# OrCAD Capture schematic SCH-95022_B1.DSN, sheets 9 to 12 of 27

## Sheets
9 Page10 BOOT CFG: size A2
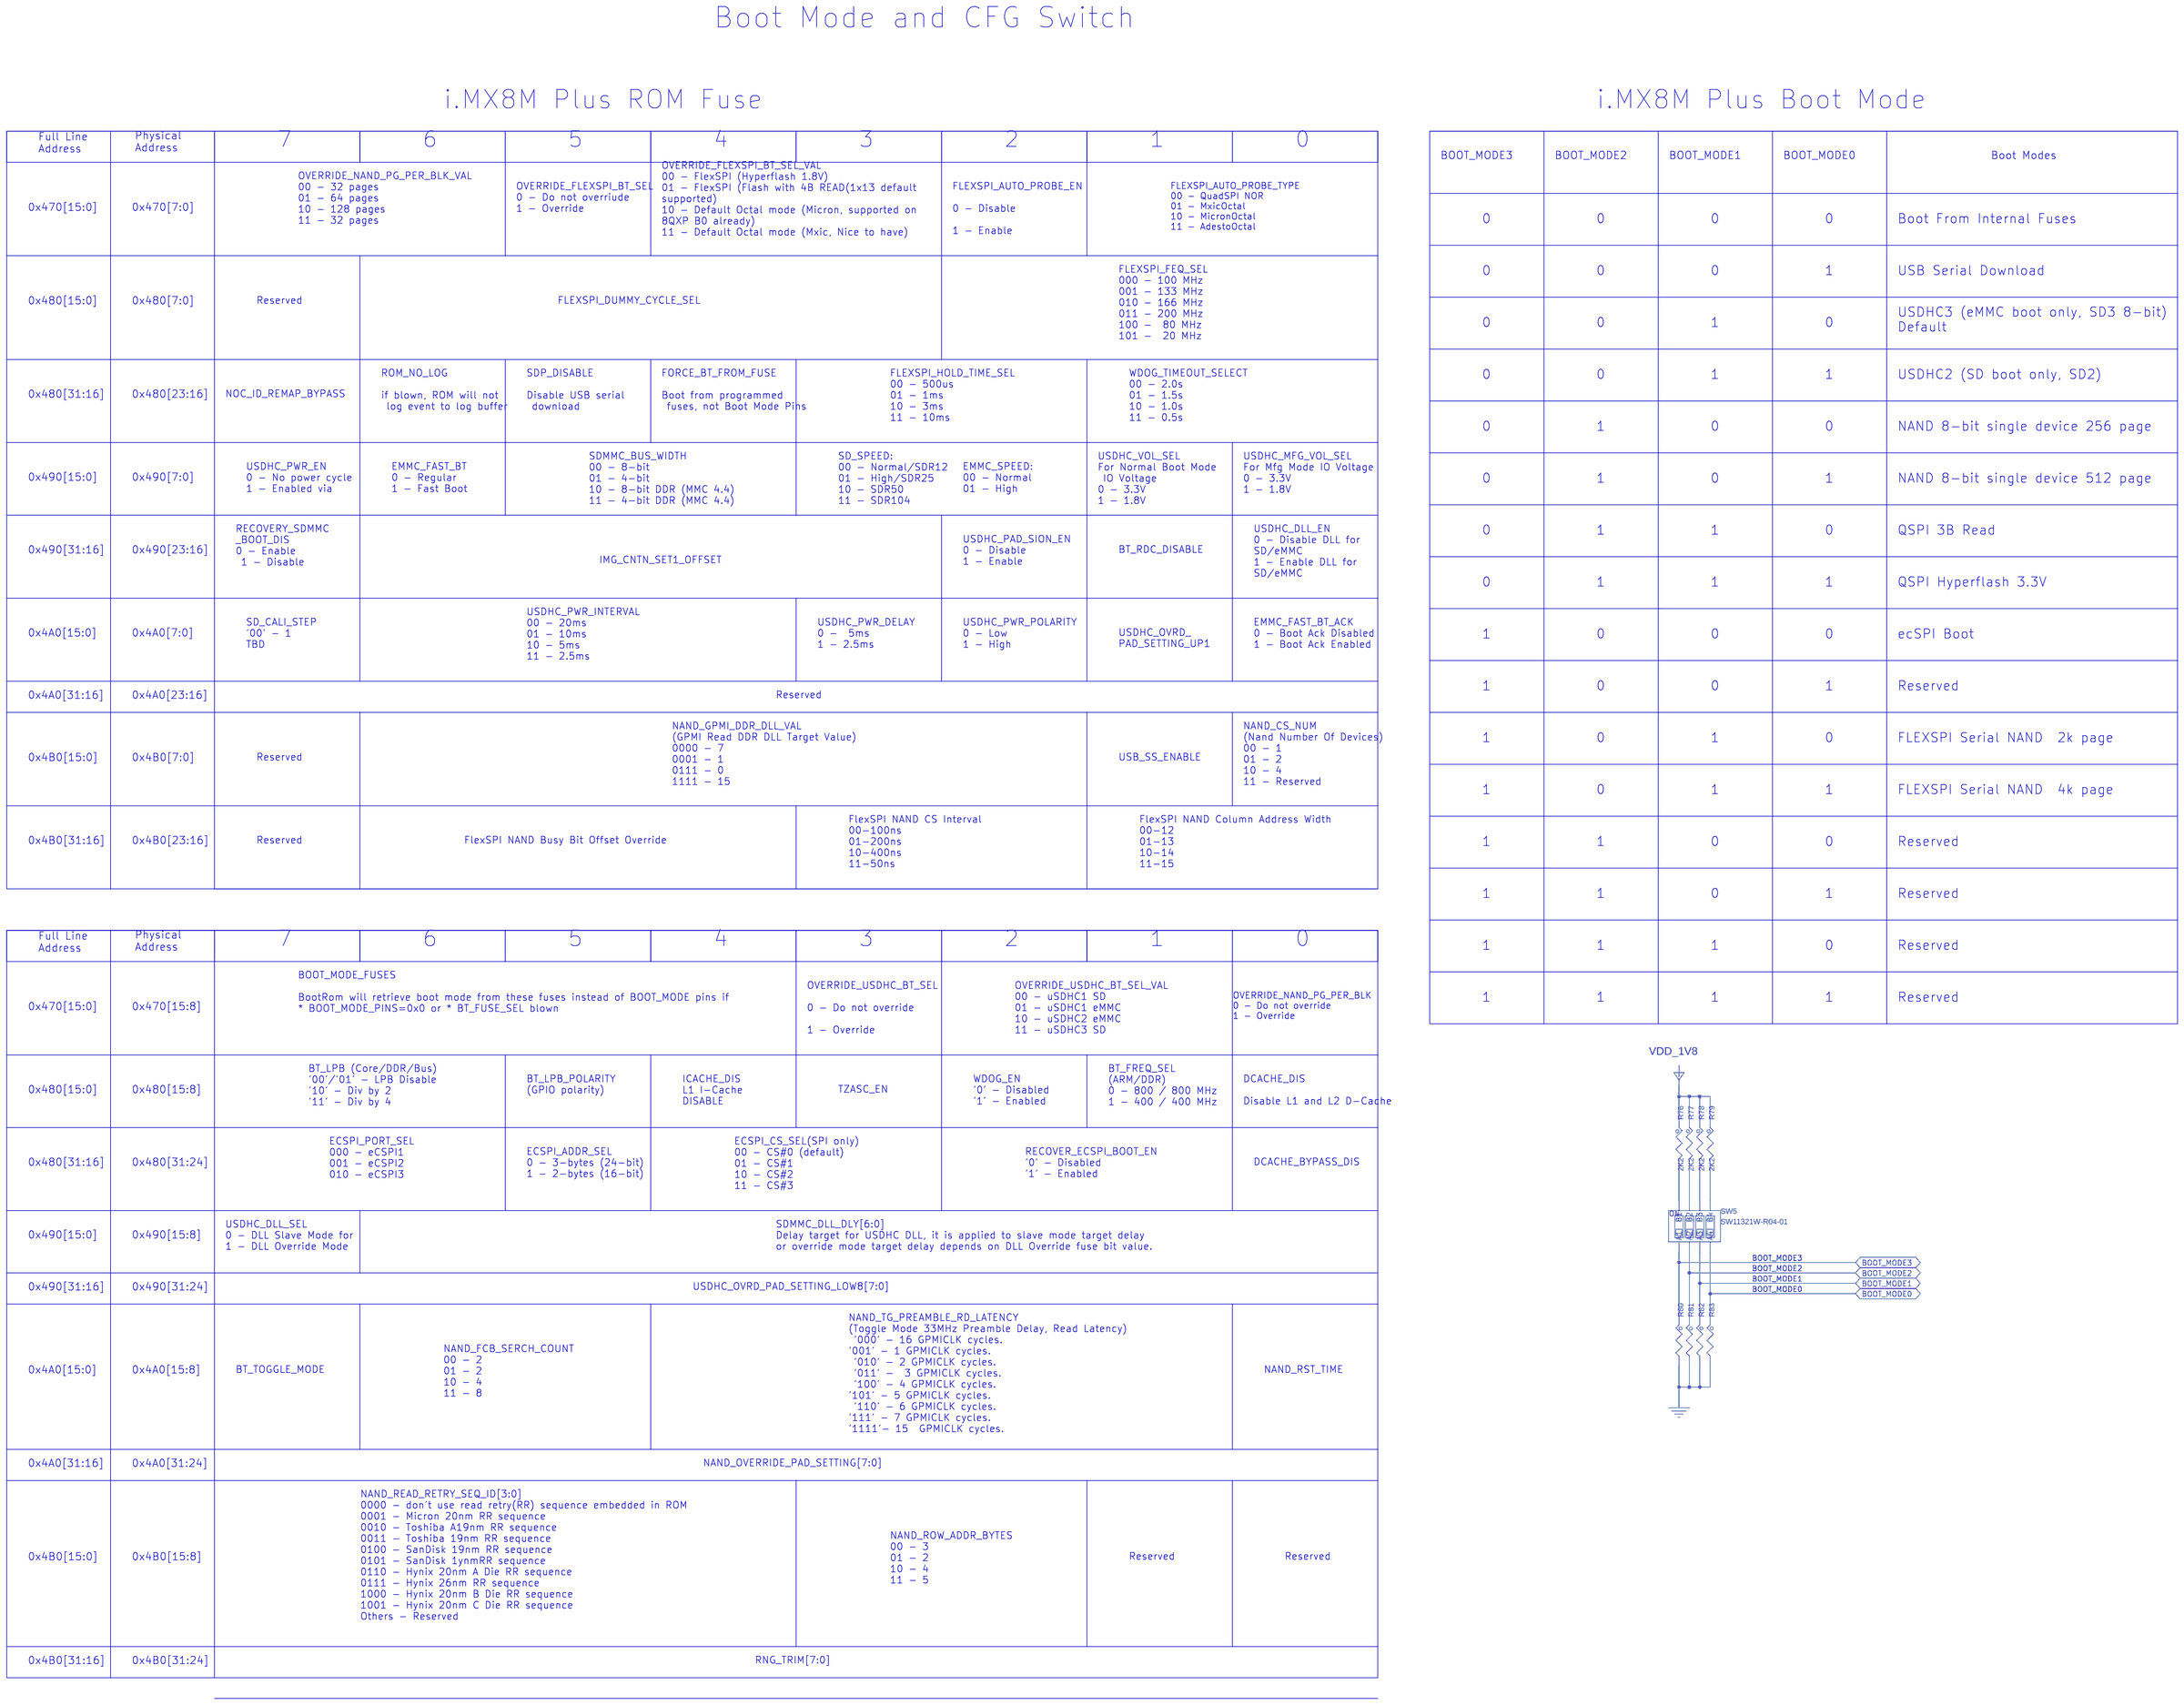
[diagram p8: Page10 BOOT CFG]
10 Page11 PMIC: size C
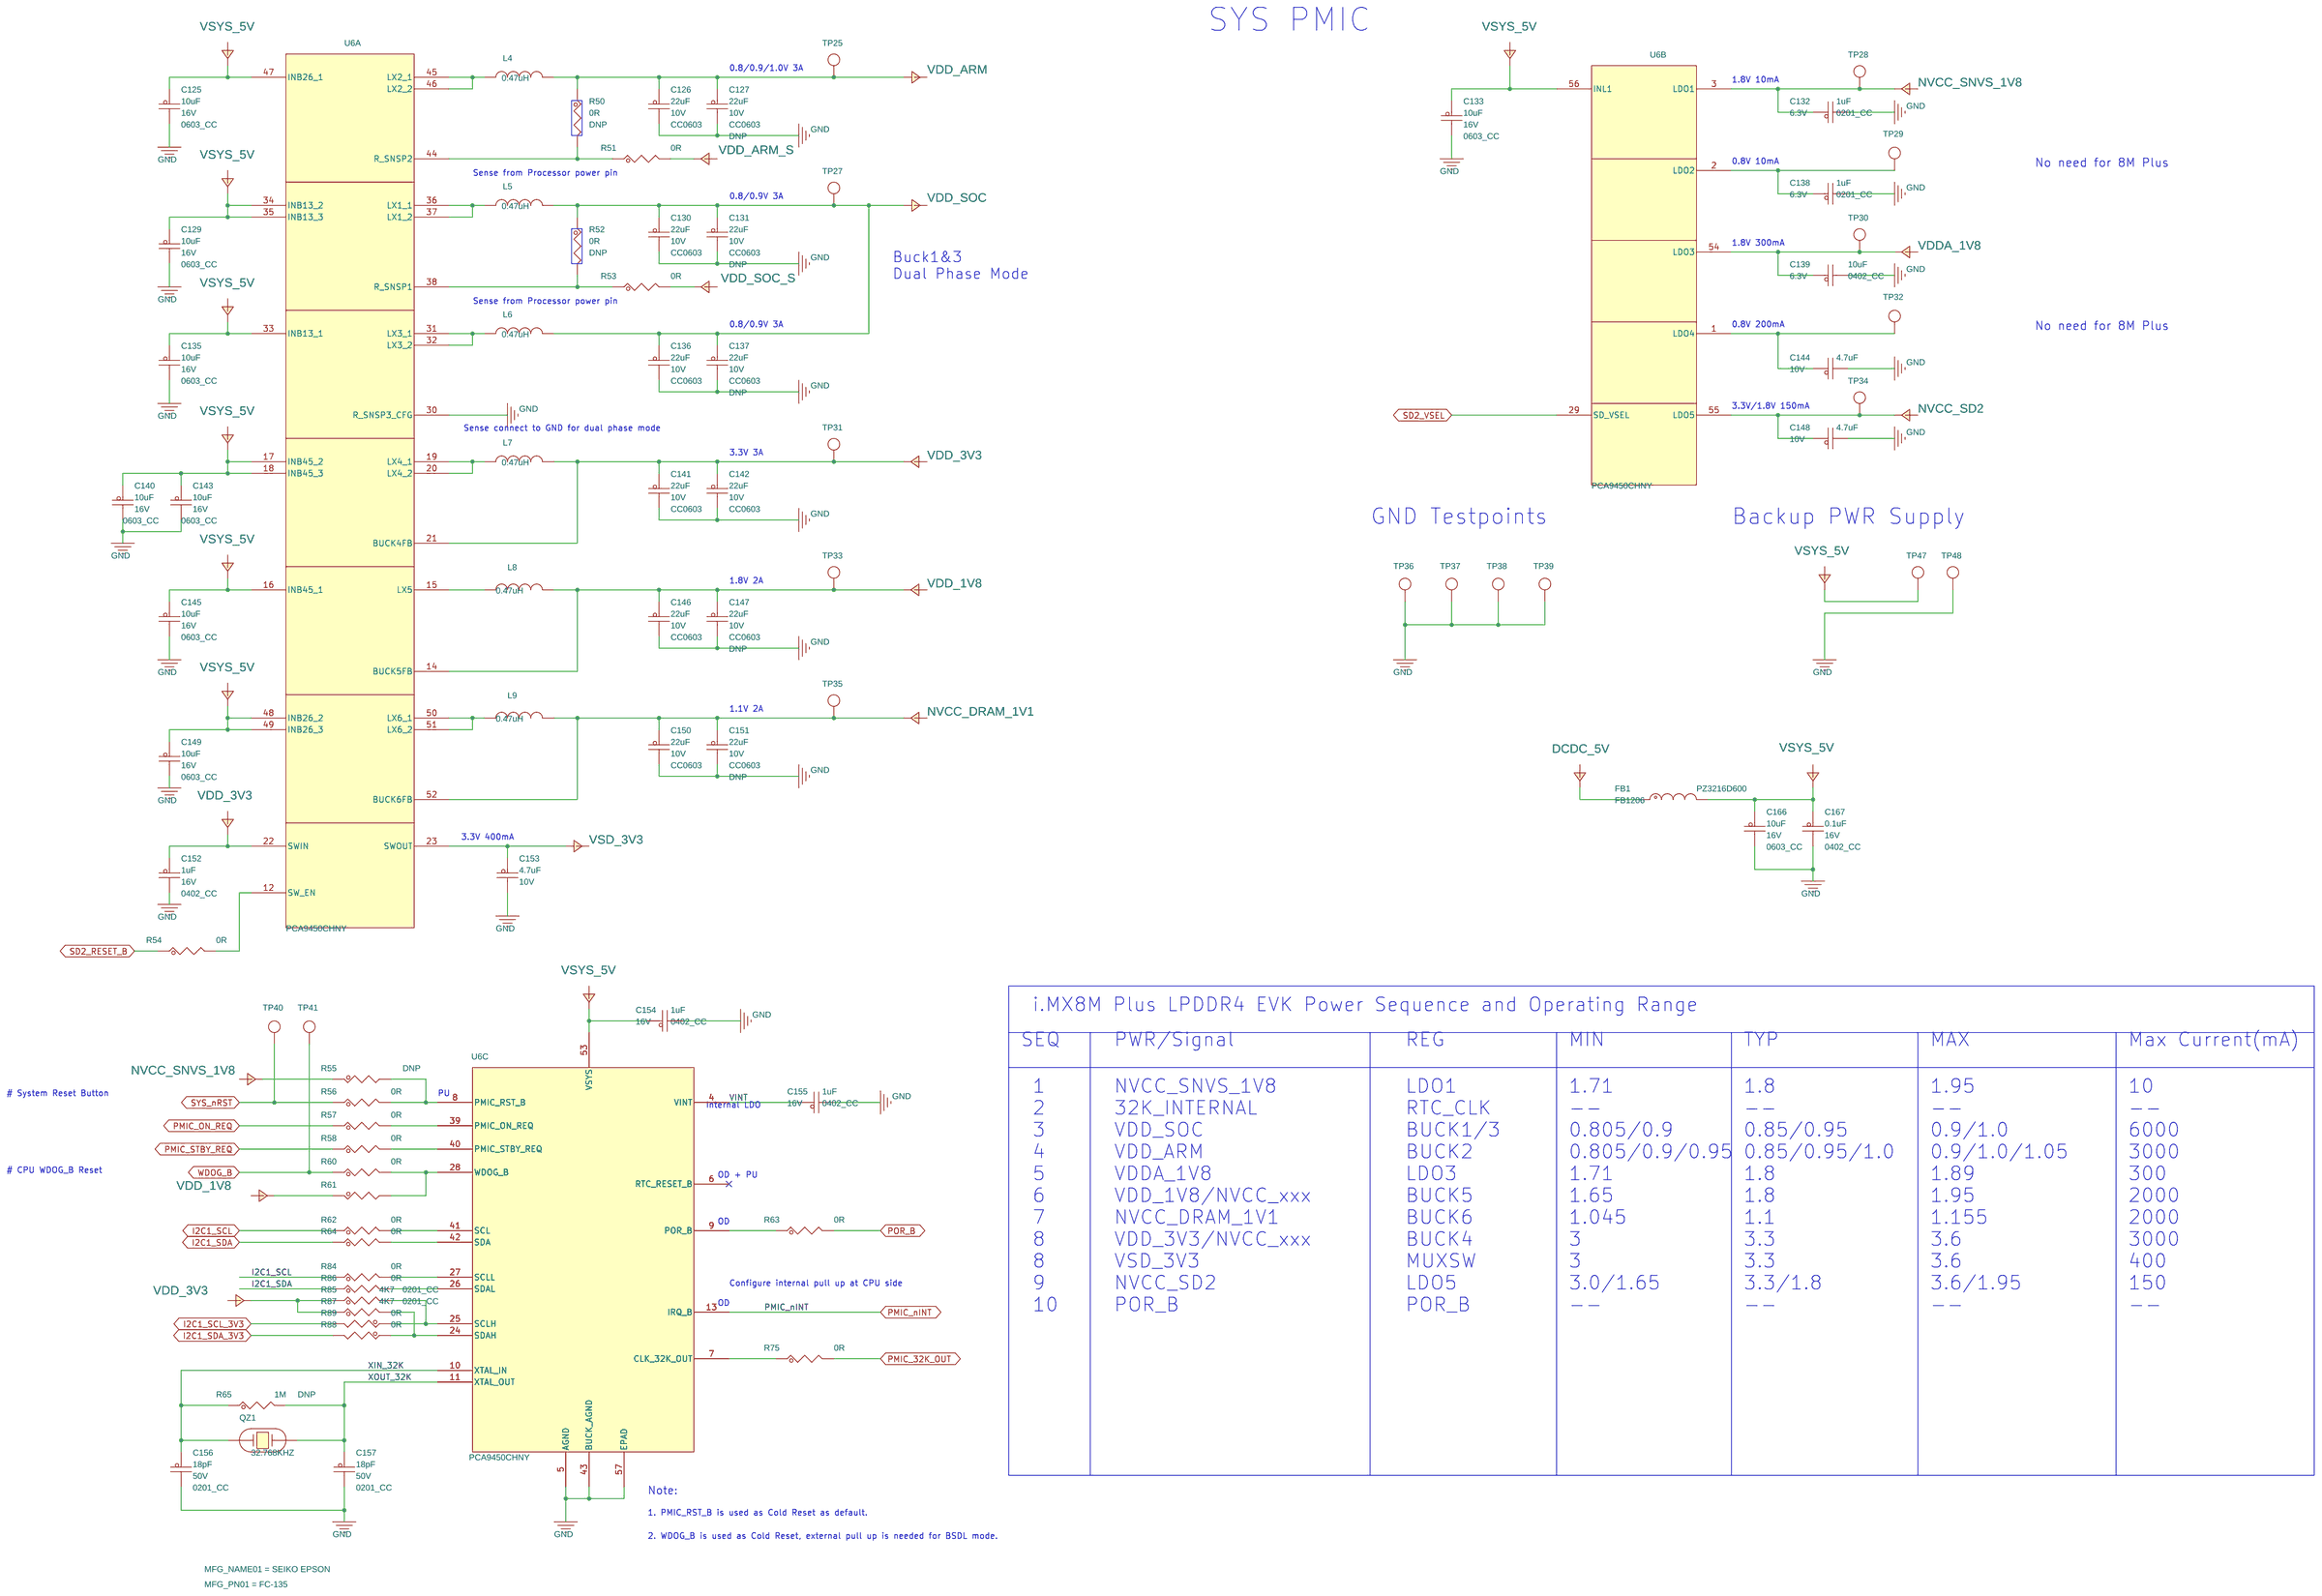
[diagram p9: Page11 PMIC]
11 Page12 SYS PWR: size C
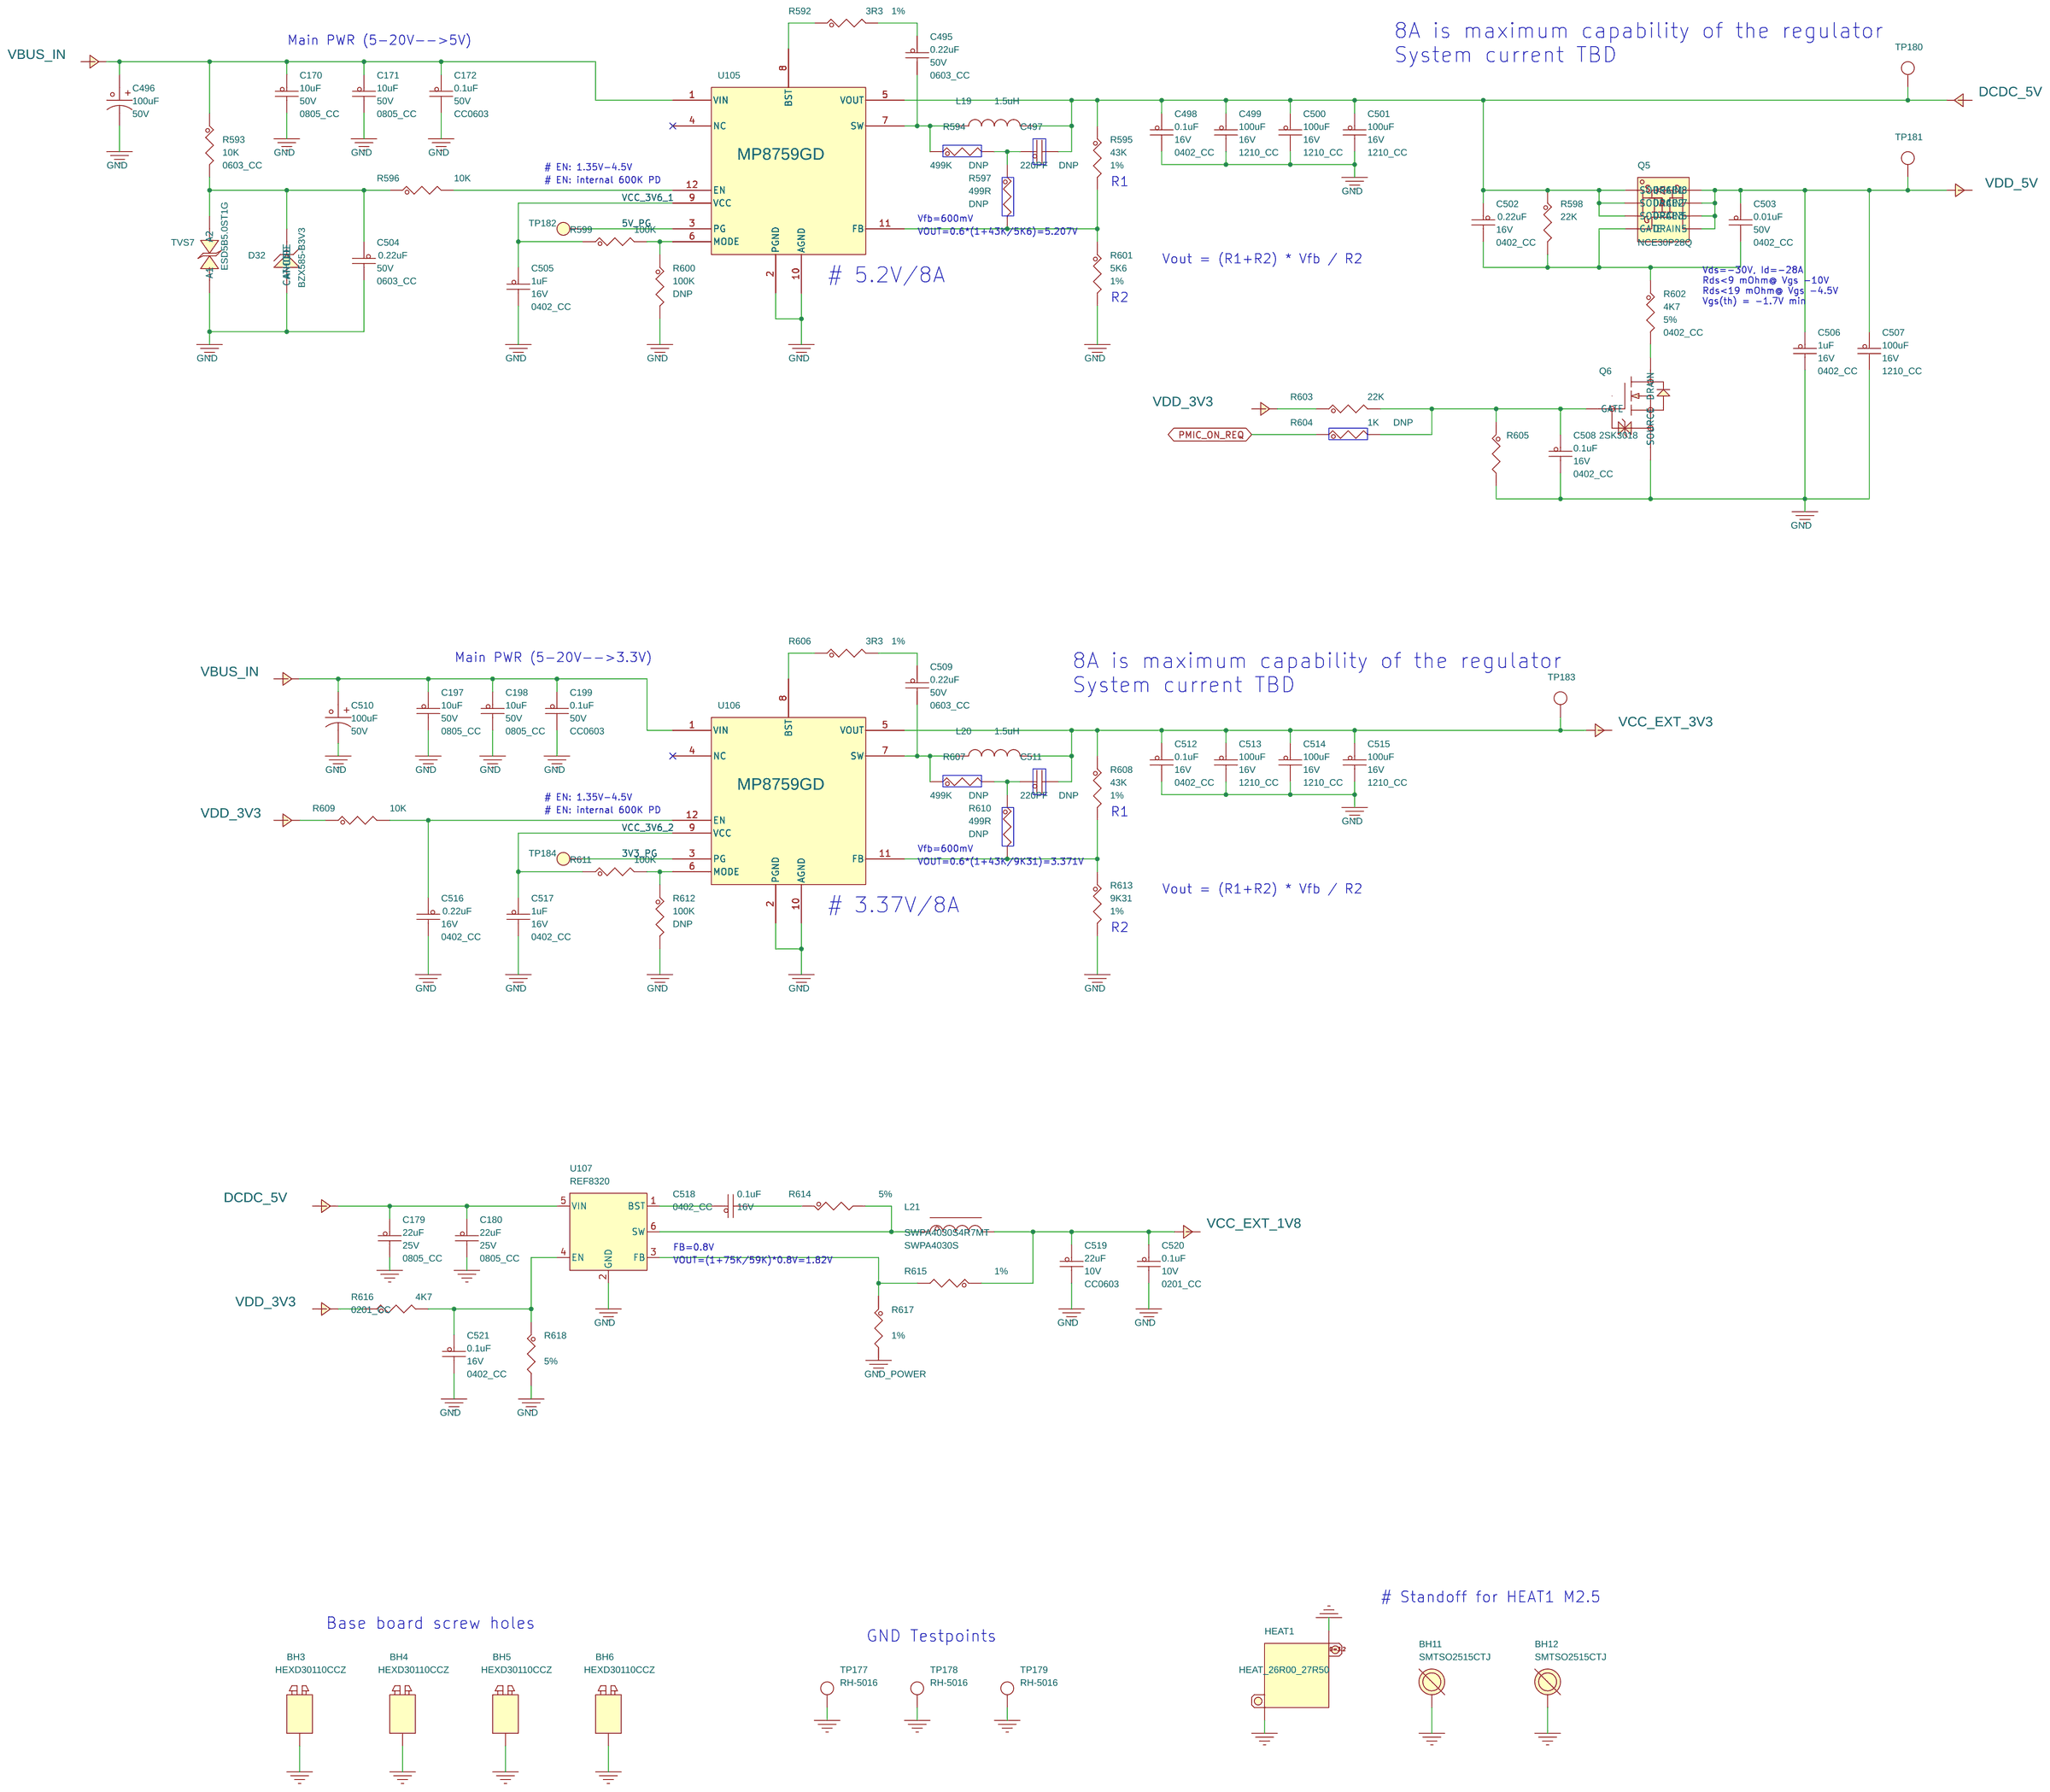
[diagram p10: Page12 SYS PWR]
12 Page13 USB PWR TYPE-C PD: size C
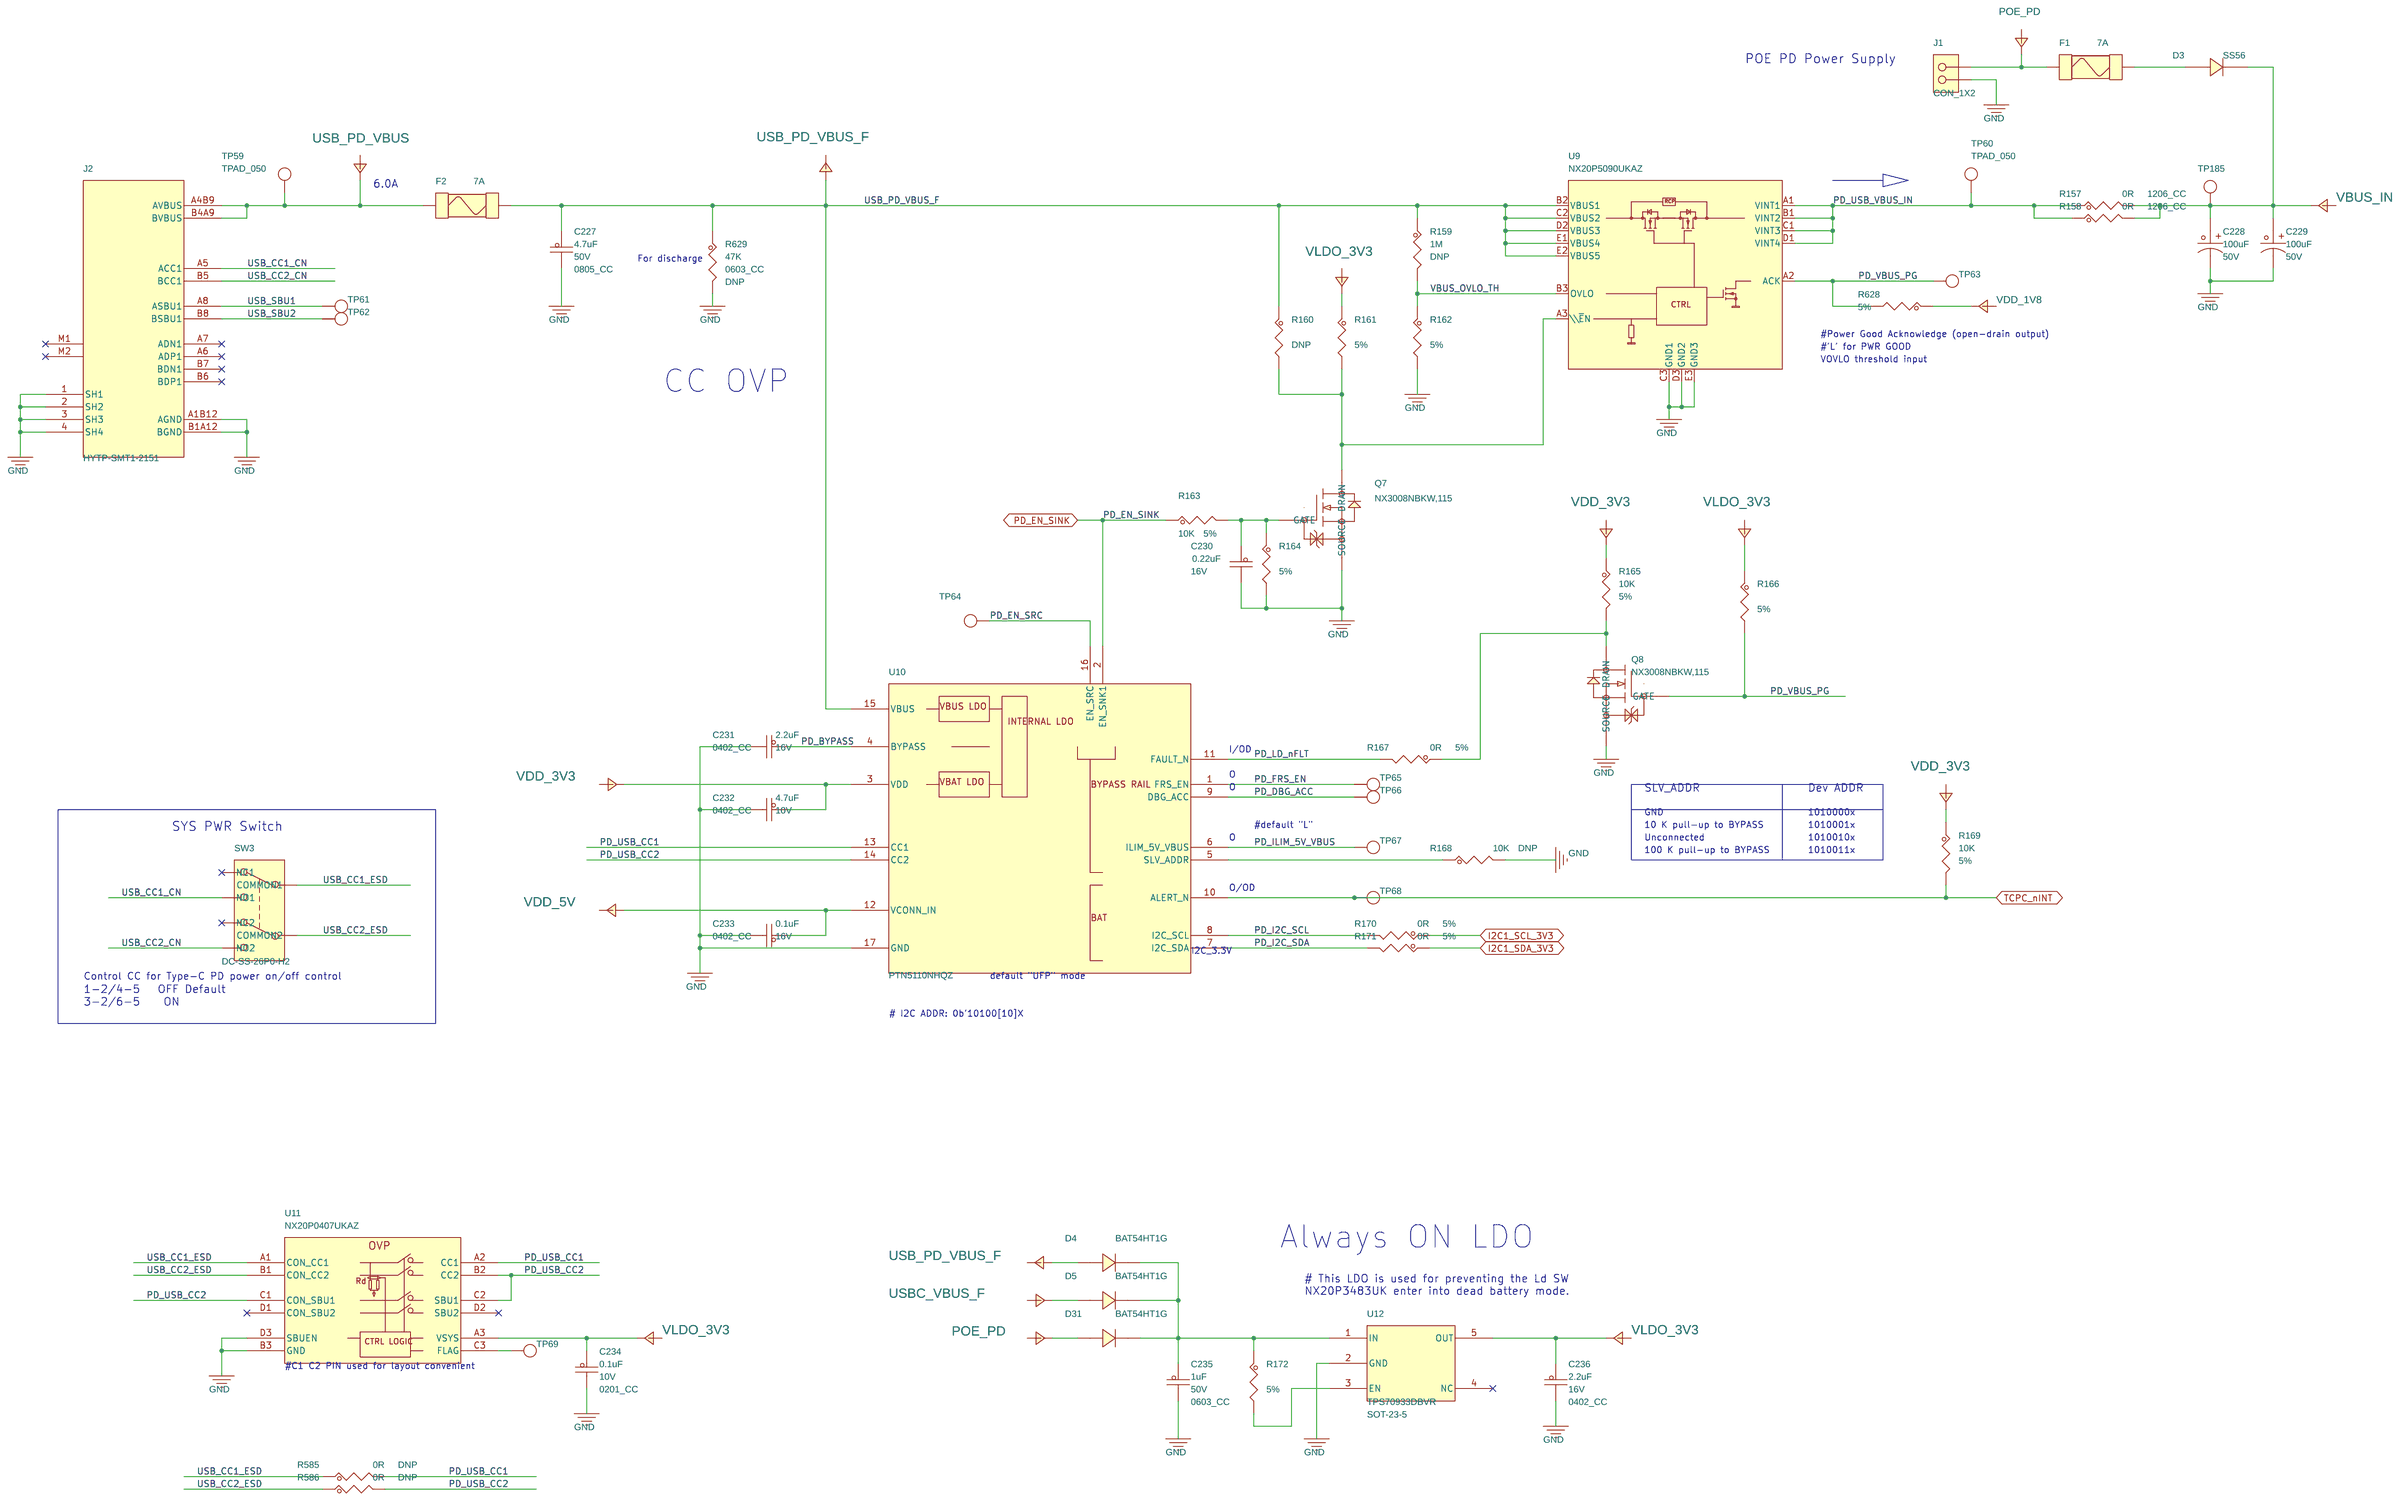
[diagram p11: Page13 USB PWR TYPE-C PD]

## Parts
sheet Page10 BOOT CFG
R76  2K2  [0402_CC]
R77  2K2  [0402_CC]
R78  2K2  [0402_CC]
R79  2K2  [0402_CC]
R80  100K  [0402_CC]
R81  100K  [0402_CC]
R82  100K  [0402_CC]
R83  100K  [0402_CC]
SW5  SW11321W-R04-01  [SW_1P27_4P]
sheet Page11 PMIC
C125  10uF  [0603_CC]
C126  22uF  [CC0603]
C127  22uF  [CC0603]
C129  10uF  [0603_CC]
C130  22uF  [CC0603]
C131  22uF  [CC0603]
C132  1uF  [0201_CC]
C133  10uF  [0603_CC]
C135  10uF  [0603_CC]
C136  22uF  [CC0603]
C137  22uF  [CC0603]
C138  1uF  [0201_CC]
C139  10uF  [0402_CC]
C140  10uF  [0603_CC]
C141  22uF  [CC0603]
C142  22uF  [CC0603]
C143  10uF  [0603_CC]
C144  4.7uF  [0402_CC]
C145  10uF  [0603_CC]
C146  22uF  [CC0603]
C147  22uF  [CC0603]
C148  4.7uF  [0402_CC]
C149  10uF  [0603_CC]
C150  22uF  [CC0603]
C151  22uF  [CC0603]
C152  1uF  [0402_CC]
C153  4.7uF  [0402_CC]
C154  1uF  [0402_CC]
C155  1uF  [0402_CC]
C156  18pF  [0201_CC]
C157  18pF  [0201_CC]
C166  10uF  [0603_CC]
C167  0.1uF  [0402_CC]
FB1  PZ3216D600  [FB1206]
L4  0.47uH  [ind_sph2520]
L5  0.47uH  [ind_sph2520]
L6  0.47uH  [ind_sph2520]
L7  0.47uH  [ind_sph2520]
L8  0.47uH  [IND_2016A]
L9  0.47uH  [IND_2016A]
QZ1  32.768KHZ  [XTAL2-3P2X1P5-SM]
R50  0R  [0402_CC]
R51  0R  [0402_CC]
R52  0R  [0402_CC]
R53  0R  [0402_CC]
R54  0R  [0402_CC]
R55  100K  [0402_CC]
R56  0R  [0402_CC]
R57  0R  [0402_CC]
R58  0R  [0402_CC]
R60  0R  [0402_CC]
R61  100K  [0402_CC]
R62  0R  [0402_CC]
R63  0R  [0402_CC]
R64  0R  [0402_CC]
R65  1M  [0402_CC]
R75  0R  [0402_CC]
R84  0R  [0402_CC]
R85  4K7  [0201_CC]
R86  0R  [0402_CC]
R87  4K7  [0201_CC]
R88  0R  [0402_CC]
R89  0R  [0402_CC]
TP25  TPAD_050  [TPAD_050]
TP27  TPAD_050  [TPAD_050]
TP28  TPAD_050  [TPAD_050]
TP29  TPAD_020  [tpad_020]
TP30  TPAD_050  [TPAD_050]
TP31  TPAD_050  [TPAD_050]
TP32  TPAD_020  [tpad_020]
TP33  TPAD_050  [TPAD_050]
TP34  TPAD_050  [TPAD_050]
TP35  TPAD_050  [TPAD_050]
TP36  TPAD_050  [TPAD_050]
TP37  TPAD_050  [TPAD_050]
TP38  TPAD_050  [TPAD_050]
TP39  TPAD_050  [TPAD_050]
TP40  TPAD_015  [TPAD_015]
TP41  TPAD_015  [TPAD_015]
TP47  TPAD_050  [TPAD_050]
TP48  TPAD_050  [TPAD_050]
U6  PCA9450CHNY  [hvqfn56_0p4_7x7_ep4p7mm]  (sections A,B,C)
sheet Page12 SYS PWR
BH3  HEXD30110CCZ  [spacer_139t]
BH4  HEXD30110CCZ  [spacer_139t]
BH5  HEXD30110CCZ  [spacer_139t]
BH6  HEXD30110CCZ  [spacer_139t]
BH11  SMTSO2515CTJ  [PTH_4R20x6R20]
BH12  SMTSO2515CTJ  [PTH_4R20x6R20]
C170  10uF  [0805_CC]
C171  10uF  [0805_CC]
C172  0.1uF  [CC0603]
C179  22uF  [0805_CC]
C180  22uF  [0805_CC]
C197  10uF  [0805_CC]
C198  10uF  [0805_CC]
C199  0.1uF  [CC0603]
C495  0.22uF  [0603_CC]
C496  100uF  [CAP_SMT_6R60X6R60X7R70]
C497  220PF  [0402_CC]
C498  0.1uF  [0402_CC]
C499  100uF  [1210_CC]
C500  100uF  [1210_CC]
C501  100uF  [1210_CC]
C502  0.22uF  [0402_CC]
C503  0.01uF  [0402_CC]
C504  0.22uF  [0603_CC]
C505  1uF  [0402_CC]
C506  1uF  [0402_CC]
C507  100uF  [1210_CC]
C508  0.1uF  [0402_CC]
C509  0.22uF  [0603_CC]
C510  100uF  [CAP_SMT_6R60X6R60X7R70]
C511  220PF  [0402_CC]
C512  0.1uF  [0402_CC]
C513  100uF  [1210_CC]
C514  100uF  [1210_CC]
C515  100uF  [1210_CC]
C516  0.22uF  [0402_CC]
C517  1uF  [0402_CC]
C518  0.1uF  [0402_CC]
C519  22uF  [CC0603]
C520  0.1uF  [0201_CC]
C521  0.1uF  [0402_CC]
D32  BZX585-B3V3  [sod523]
HEAT1  HEAT_26R00_27R50  [H_26R00_27R50]
L19  1.5uH  [IND_IHLP]
L20  1.5uH  [IND_IHLP]
L21  SWPA4030S4R7MT  [SWPA4030S]
Q5  NCE30P28Q  [DFN_3x3-8L]
Q6  2SK3018  [SOT_323]
R592  3R3  [0603_CC]
R593  10K  [0603_CC]
R594  499K  [0402_CC]
R595  43K  [0402_CC]
R596  10K  [0402_CC]
R597  499R  [0402_CC]
R598  22K  [0402_CC]
R599  100K  [0402_CC]
R600  100K  [0402_CC]
R601  5K6  [0402_CC]
R602  4K7  [0402_CC]
R603  22K  [0402_CC]
R604  1K  [0402_CC]
R605  100K  [0402_CC]
R606  3R3  [0603_CC]
R607  499K  [0402_CC]
R608  43K  [0402_CC]
R609  10K  [0402_CC]
R610  499R  [0402_CC]
R611  100K  [0402_CC]
R612  100K  [0402_CC]
R613  9K31  [0402_CC]
R614  33R  [0402_CC]
R615  75K  [0402_CC]
R616  4K7  [0201_CC]
R617  59K  [0402_CC]
R618  100K  [0402_CC]
TP177  RH-5016  [TEST_PIN_TP107]
TP178  RH-5016  [TEST_PIN_TP107]
TP179  RH-5016  [TEST_PIN_TP107]
TP180  TPAD_050  [TPAD_050]
TP181  TPAD_050  [TPAD_050]
TP182  TP_35MIL  [testpoint_35mil]
TP183  TPAD_050  [TPAD_050]
TP184  TP_35MIL  [testpoint_35mil]
TVS7  ESD5B5.0ST1G  [diode2_sod523]
U105  MP8759GD  [qfn12_0p5_3p1x2p1]
U106  MP8759GD  [qfn12_0p5_3p1x2p1]
U107  REF8320  [SOT23-6]
sheet Page13 USB PWR TYPE-C PD
C227  4.7uF  [0805_CC]
C228  100uF  [CAP_SMT_6R60X6R60X7R70]
C229  100uF  [CAP_SMT_6R60X6R60X7R70]
C230  0.22uF  [0402_CC]
C231  2.2uF  [0402_CC]
C232  4.7uF  [0402_CC]
C233  0.1uF  [0402_CC]
C234  0.1uF  [0201_CC]
C235  1uF  [0603_CC]
C236  2.2uF  [0402_CC]
D3  SS56  [SMA]
D4  BAT54HT1G  [SOD323]
D5  BAT54HT1G  [SOD323]
D31  BAT54HT1G  [SOD323]
F1  7A  [fuse_3p4x1p8]
F2  7A  [fuse_3p4x1p8]
J1  CON_1X2  [con2_2p5_7p96x5p96_th]
J2  HYTP-SMT1-2151  [TYPEC16P_8P94X7P30X3P16]
Q7  NX3008NBKW,115  [sc70_3]
Q8  NX3008NBKW,115  [sc70_3]
R157  0R  [1206_CC]
R158  0R  [1206_CC]
R159  1M  [0402_CC]
R160  100K  [0402_CC]
R161  100K  [0402_CC]
R162  100K  [0402_CC]
R163  10K  [0402_CC]
R164  100K  [0402_CC]
R165  10K  [0402_CC]
R166  100K  [0402_CC]
R167  0R  [0402_CC]
R168  10K  [0402_CC]
R169  10K  [0402_CC]
R170  0R  [0402_CC]
R171  0R  [0402_CC]
R172  100K  [0402_CC]
R585  0R  [0201_CC]
R586  0R  [0201_CC]
R628  100K  [0402_CC]
R629  47K  [0603_CC]
SW3  DC-SS-26P0-H2  [SW_DIP_9R00x3R50x5R50]
TP59  TPAD_050  [TPAD_050]
TP60  TPAD_050  [TPAD_050]
TP61  TPAD_020  [tpad_020]
TP62  TPAD_020  [tpad_020]
TP63  TPAD_020  [tpad_020]
TP64  TPAD_020  [tpad_020]
TP65  TPAD_020  [tpad_020]
TP66  TPAD_020  [tpad_020]
TP67  TPAD_020  [tpad_020]
TP68  TPAD_020  [tpad_020]
TP69  TPAD_020  [tpad_020]
TP185  TPAD_050  [TPAD_050]
U9  NX20P5090UKAZ  [wlcsp15_0p5_1p57x2p59]
U10  PTN5110NHQZ  [hx2qfn16_0p4_2p7x2p7]
U11  NX20P0407UKAZ  [wlcsp12_0p4_1p3x1p7mm_smdp]
U12  TPS70933DBVR  [SOT-23-5]

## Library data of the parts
R76-R79 = RES: RES MF 2K2 1/16W 5% 0402; CAD_APPROVED: Yes; HEIGHT: 0.23mm; MFG_NAME01: YAGEO; MFG_PN01: RC0402JR-072K2L; Polyhex_Number: PD.004.0098; ROHS: Yes; Tolerance: 5%; VOLTAGE: 50V
R61 R80-R83 R161 R162 R164 R166 R172 R599 R605 R611 R618 R628 = RES: RES MF 100K 1/16W 5% 0402; AGILE_PN: 470-75597; CAD_APPROVED: Yes; FPLIST: RC0402_25,RC0402_HD,0402_CC; HEIGHT: 0.40 MM; MFG_NAME01: YAGEO; MFG_PN01: RC0402JR-07100KL; Polyhex_Number: PD.004.0004; ROHS: Yes; Temp Range: -55C to +155C; Temp_Range: -55C to +155C; Tolerance: 5%; VOLTAGE: 50V
SW5 = SW_1P27_4P: SW 4P SPST DIP 25MA 24V SMT; MFG_NAME01: JINRUN; Polyhex_Number: PD.010.0164
C125 C129 C133 C135 C140 C143 C145 C149 C166 = CAP_NP: CAP CER 10uF 16V 10% X5R 0603; CAD_APPROVED: Yes; HEIGHT: 0.55 MM; MFG_NAME01: SAMSUNG; MFG_PN01: CL10A106MO8NQN; Package Size: 0603; Polyhex_Number: PD.005.0001; ROHS: Yes; Tolerance: 10%; VOLTAGE: 16V
C126 C130 C136 C141 C142 C146 C150 C519 = CAP_NP: CAP CER 22uF 10V 20% X5R 0603; AGILE_PN: 150-79530; CAD_APPROVED: Yes; FPLIST: CC0603_OV,CC0603,0603_CC; HEIGHT: 1MM; MFG_NAME01: SAMSUNG; MFG_PN01: CL10A226MP8NUNE; Package Size: 0603; Polyhex_Number: PD.005.0003; ROHS: Yes; SIGNAL_MODEL: DEFAULT_CAPACITOR_2.2e+07pF_2_1; Tolerance: 20%; VOLTAGE: 10V; WVDC: 6.3V
C127 C131 C137 C147 C151 = CAP_NP: CAP CER 22uF 10V 20% X5R 0603; AGILE_PN: 150-79530; ASSY_OPT: DNP; CAD_APPROVED: Yes; FPLIST: CC0603_OV,CC0603,0603_CC; HEIGHT: 1MM; MFG_NAME01: SAMSUNG; MFG_PN01: CL10A226MP8NUNE; Package Size: 0603; Polyhex_Number: PD.005.0003; ROHS: Yes; SIGNAL_MODEL: DEFAULT_CAPACITOR_2.2e+07pF_2_1; Tolerance: 20%; VOLTAGE: 10V; WVDC: 6.3V
C132 C138 = CAP_NP: CAP CER 1uF 6.3V 10% X5R 0201; AGILE_PN: 150-79407; CAD_APPROVED: Yes; FPLIST: CC0201,CC0201_HD,0201_CC,0201_CC_012SM_NSP; HEIGHT: 0.35MM; MFG_NAME01: SAMSUNG; MFG_PN01: CL03A105KQ3CSNH; Package Size: 0201; Package Type: 7” reel; Polyhex_Number: PD.005.0030; ROHS: Yes; Tolerance: 10%; VOLTAGE: 6.3V
C139 = CAP_NP: CAP CER 10UF 6.3V 20% X5R 0402; AGILE_PN: 150-79163; CAD_APPROVED: Yes; FPLIST: CC0402_25,CC0402_HD,0402_CC; HEIGHT: 0.65 MM; MFG_NAME01: SAMSUNG; MFG_PN01: CL05A106MQ5NUNC; Polyhex_Number: PD.005.0031; ROHS: Yes; Tolerance: 20%; VOLTAGE: 6.3V
C144 C148 C153 C232 = CAP_NP: CAP CER 4.7uF 10V 10% X5R 0402; CAD_APPROVED: Yes; HEIGHT: 0.95MM; MFG_NAME01: SAMSUNG; MFG_PN01: CL05A475KP5NRNC; Polyhex_Number: PD.005.0058; ROHS: Yes; Temp Range: -55°C to + 85°C; Tolerance: 10%; VOLTAGE: 10V
C152 C154 C155 C505 C506 C517 = CAP_NP: CAP CER 1UF 16V 10% X5R 0402; CAD_APPROVED: Yes; FPLIST: CC0402_25,CC0402_HD,0402_CC,capc0402_l; HEIGHT: 0.55MM; MFG_NAME01: SAMSUNG; MFG_PN01: CL05A105KO5NNNC; Polyhex_Number: PD.005.0099; ROHS: Yes; Tolerance: 10%; VOLTAGE: 16V
C156 C157 = CAP_NP: CAP CER 18pF 50V 5% C0G 0201; CAD_APPROVED: Yes; HEIGHT: 0.35MM; MFG_NAME01: SAMSUNG; MFG_PN01: CL03C180JB3NNNH; Package Size: 0201; Package Type: 7” reel; Polyhex_Number: PD.005.0033; ROHS: Yes; Tolerance: 5%; VOLTAGE: 50V
C167 C233 C498 C508 C512 C518 C521 = CAP_NP: CAP CER 0.1UF 16V 10% X5R 0402; CAD_APPROVED: Yes; FPLIST: CC0402_25,CC0402_HD,0402_CC,capc0402_l; HEIGHT: 0.55MM; MFG_NAME01: SAMSUNG; MFG_PN01: CL05B104K05NNNC; Polyhex_Number: PD.005.0036; ROHS: Yes; Tolerance: 10%; VOLTAGE: 16V
FB1 = Ferrite_Bead: FERRITE 1206 60Ohm@100MHz 4A; HEIGHT: 0.5mm; Irms: <Irms>; MFG_NAME01: Sunlord; Polyhex_Number: PD.009.0003; Temp Range: -55C to +125C; Temp_Range: -55C to +125C
L4-L7 = INDUCTOR: IND PWR 0.47uH@1MHZ 4.7A 20% SMT; AGILE_PN: 180-78647; CAD_APPROVED: Yes; HEIGHT: 1.2MM; MFG_NAME01: SUNLORD; MFG_PN01: WPN252012HR47MT; PART_TYPE: INDUCTOR\POWER; Polyhex_Number: PD.012.0005; ROHS: Yes; TOL: 20%; Temp Range: -40°C to +125°C; Temp_Range: -40°C to +125°C; Tolerance: 20%
L8 L9 = INDUCTOR: IND PWR 0.47uH@1MHz 3.4A 20% 2016; AGILE_PN: 180-78995; CAD_APPROVED: Yes; HEIGHT: 1.2MM; MFG_NAME01: SUNLORD; MFG_PN01: WPN201610HR47MT; PART_TYPE: INDUCTOR\POWER; Package Size: 2x1.6x1.2 mm; Polyhex_Number: PD.012.0006; ROHS: Yes; Temp Range: -40°C to 125°C; Temp_Range: -40°C to 125°C; Tolerance: 20%
QZ1 = XTAL: XTAL 32.768KHZ 12.5PF 20PPM 3.2X1.5MM SMT; AGILE_PN: 230-77653; CAD_APPROVED: Yes; HEIGHT: 0.9MM; MFG_NAME01: SEIKO EPSON; MFG_PN01: FC-135; Polyhex_Number: PD.018.0003; ROHS: Yes; Temp Range: -40C to +85C; Temp_Range: -40C to +85C; Tolerance: 20PPM
R50 R52 = RES: RES MF ZERO OHM 1/16W 5% 0402; AGILE_PN: 470-75394; ASSY_OPT: DNP; CAD_APPROVED: Yes; FPLIST: RC0402_25,RC0402_HD,RC0402_X2,0402_CC; HEIGHT: 0.45 MM; MFG_NAME01: YAGEO; MFG_PN01: RC0402JR-070RL; Polyhex_Number: PD.004.0009; ROHS: Yes; Tolerance: 5%; VOLTAGE: 50V
R51 R53 R54 R56 R58 R60 R62 R64 R84 R86 R88 R89 R167 R170 R171 = RES: RES MF ZERO OHM 1/16W 5% 0402; AGILE_PN: 470-75394; CAD_APPROVED: Yes; FPLIST: RC0402_25,RC0402_HD,RC0402_X2,0402_CC; HEIGHT: 0.45 MM; MFG_NAME01: YAGEO; MFG_PN01: RC0402JR-070RL; Polyhex_Number: PD.004.0009; ROHS: Yes; Tolerance: 5%; VOLTAGE: 50V
R55 R160 R600 R612 = RES: RES MF 100K 1/16W 5% 0402; AGILE_PN: 470-75597; ASSY_OPT: DNP; CAD_APPROVED: Yes; FPLIST: RC0402_25,RC0402_HD,0402_CC; HEIGHT: 0.40 MM; MFG_NAME01: YAGEO; MFG_PN01: RC0402JR-07100KL; Polyhex_Number: PD.004.0004; ROHS: Yes; Temp Range: -55C to +155C; Temp_Range: -55C to +155C; Tolerance: 5%; VOLTAGE: 50V
R57 R63 R75 = RES: RES MF ZERO OHM 1/16W 5% 0402; AGILE_PN: 470-75394; CAD_APPROVED: Yes; HEIGHT: 0.45 MM; MFG_NAME01: YAGEO; MFG_PN01: RC0402JR-070RL; Polyhex_Number: PD.004.0009; ROHS: Yes; Tolerance: 5%; VOLTAGE: 50V
R65 R159 = RES: RES MF 1M 1/16W 1% 0402; AGILE_PN: 470-80575; ASSY_OPT: DNP; CAD_APPROVED: Yes; FPLIST: RC0402_25,RC0402_HD,0402_CC; HEIGHT: 0.4MM; MFG_NAME01: YAGEO; MFG_PN01: RC0402FR-071ML; Polyhex_Number: PD.004.0230; ROHS: Yes; Tolerance: 1%
R85 R87 R616 = RES: RES MF 4K7 1/20W 5% 0201; AGILE_PN: 470-82323; CAD_APPROVED: Yes; FPLIST: RC0201,0201_CC; HEIGHT: 0.26MM; MFG_NAME01: YAGEO; MFG_PN01: RC0201JR-074K7L; Polyhex_Number: PD.004.0072; ROHS: Yes; Temp Range: -55°C ~ 125°C; Temp_Range: -55°C ~ 125°C; Tolerance: 5%; VOLTAGE: 25V
TP25 TP27 TP28 TP30 TP31 TP33-TP35 TP47 TP48 TP185 = TestLoop: TEST POINT PAD 50MIL DIA SMT, NO PART TO ORDER; AGILE_PN: 211-76644; ASSY_OPT: DNP; CAD_APPROVED: Yes; HEIGHT: 0.1MM; MFG_NAME01: NOTACOMPONENT; MFG_PN01: NOTACOMPONENT; Polyhex_Number: TEST POINT; ROHS: Yes
TP29 TP32 TP61-TP69 = TESTLOOP: TEST POINT PAD 0.5MM DIA SMT, NO PART TO ORDER; AGILE_PN: 211-77484; ASSY_OPT: DNP; CAD_APPROVED: Yes; HEIGHT: 0.1MM; MFG_NAME01: NOT A COMPONENT; MFG_PN01: NOT A COMPONENT; Polyhex_Number: TEST POINT; ROHS: Yes
TP36-TP39 TP59 TP60 TP180 TP181 TP183 = TESTLOOP: TEST POINT PAD 50MIL DIA SMT, NO PART TO ORDER; AGILE_PN: 211-76644; ASSY_OPT: DNP; CAD_APPROVED: Yes; HEIGHT: 0.1MM; MFG_NAME01: NOTACOMPONENT; MFG_PN01: NOTACOMPONENT; Polyhex_Number: TEST POINT; ROHS: Yes
TP40 TP41 = TestLoop: TEST POINT PAD 15MIL DIA SMT, NO PART TO ORDER; AGILE_PN: 211-76645; ASSY_OPT: DNP; CAD_APPROVED: Yes; HEIGHT: 0.1MM; MFG_NAME01: NOT A COMPONENT; MFG_PN01: NOT A COMPONENT; Polyhex_Number: TEST POINT; ROHS: Yes
U6 = PCA9450_HVQFN56P_A: IC POWER MANAGEMENT 2.7-5.5V HVQFN56; AGILE_PN: TMP-WF-36306; HEIGHT: 1MM; MFG_NAME01: NXP SEMICONDUCTORS; PRE_APN: 315-82348; Polyhex_Number: PD.008.0105; ROHS: Yes; Temp Range: -40C to +105C; Temp_Range: -40C to +105C; VOLTAGE: 2.7-5.5V
BH3-BH6 = SPACER: HEX FEMALE TO FEMALE STANDOFFS BRASS 11MM LENGTH; AGILE_PN: 280-76498; ASSY_OPT: DNP; CAD_APPROVED: Yes; HEIGHT: 16.13MM; MFG_NAME01: SINHOOST; Polyhex_Number: PD.019.00xx; ROHS: Yes
BH11 BH12 = MOUNT_HOLE: FASTENER STANDOFF M2.5 Length-1.5mm; AGILE_PN: 280-77165; CAD_APPROVED: Yes; HEIGHT: 1.5MM; MFG_NAME01: SINHOOST; Polyhex_Number: PD.019.0019; ROHS: Yes
C170 C171 C197 C198 = CAP_NP: CAP CER 10UF 50V 10% X5R 0805; CAD_APPROVED: Yes; MFG_NAME01: SAMSUNG; MFG_PN01: CL21A106KBYQNNE; Polyhex_Number: PD.005.0060; ROHS: Yes; Tolerance: 10%; VOLTAGE: 50V
C172 C199 = CAP_NP: CAP CER 0.1uF 50V 10% X7R 0603; CAD_APPROVED: Yes; MFG_NAME01: SAMSUNG; MFG_PN01: CL10B104KB8NNNC; Polyhex_Number: PD.005.0061; ROHS: Yes; Tolerance: 10%; VOLTAGE: 50V
C179 C180 = CAP_NP: CAP CER 22uF 25V 20% X5R 0805; CAD_APPROVED: Yes; HEIGHT: 0.95MM; MFG_NAME01: SAMSUNG; MFG_PN01: CL21A226MAQNNNE; Polyhex_Number: PD.005.0098; ROHS: Yes; Temp Range: -55°C to + 85°C; Tolerance: 20%; VOLTAGE: 25V
C495 C504 C509 = CAP_NP: CAP CER 0.22uF 50V 10% X5R 0603; AGILE_PN: 150-79999; CAD_APPROVED: Yes; FPLIST: CC0402_25,CC0402_HD,0402_CC; HEIGHT: 0.55MM; MFG_NAME01: SAMSUNG; MFG_PN01: CL10B224KB8NNNC; Package Size: 0402; Polyhex_Number: PD.005.0118; ROHS: Yes; Temp Range: -55°C to +85°C; Temp_Range: -55°C to +85°C; Tolerance: 10%; VOLTAGE: 50V
C228 C229 C496 C510 = CAP_POL: CAP ALEL 100uF 50V 20% -- SMD; AGILE_PN: 150-79137; CAD_APPROVED: Yes; HEIGHT: 7.7MM; MFG_NAME01: HONORCAP; MFG_PN01: VP1H101M0607; Polyhex_Number: PD.005.0134; ROHS: Yes; SILK: RVT; Tolerance: 20%; VOLTAGE: 50V
C497 C511 = CAP_NP: CAP CER 220pF 50V 10% X7R 0402; AGILE_PN: 150-30297; ASSY_OPT: DNP; CAD_APPROVED: Yes; FPLIST: CC0402_25,CC0402_HD,0402_CC; HEIGHT: 0.55MM; MFG_NAME01: SAMSUNG; MFG_PN01: CL05B221KB5NNNC; Package Size: 0402; Polyhex_Number: PD.005.0028; ROHS: Yes; Tolerance: 10%; VOLTAGE: 50V
C499-C501 C507 C513-C515 = CAP_NP: CAP CER 100uF 16V 20% X5R 1210; AGILE_PN: 150-79142; CAD_APPROVED: Yes; FPLIST: CC1210,1210_CC; HEIGHT: 2.8MM; MFG_NAME01: TAIYO YUDEN; MFG_PN01: EMK325ABJ107MM-T; Package Size: 1210; Polyhex_Number: PD.005.0132; ROHS: Yes; Tolerance: 20%; VOLTAGE: 16V
C230 C502 C516 = CAP_NP: CAP CER 0.22uF 16V 10% X5R 0402; AGILE_PN: 150-79999; CAD_APPROVED: Yes; FPLIST: CC0402_25,CC0402_HD,0402_CC; HEIGHT: 0.55MM; MFG_NAME01: SAMSUNG; MFG_PN01: CL05B224KO5NNNC; Package Size: 0402; Polyhex_Number: PD.005.0050; ROHS: Yes; Temp Range: -55°C to +85°C; Temp_Range: -55°C to +85°C; Tolerance: 10%; VOLTAGE: 16V
C503 = CAP_NP: CAP CER 0.01uF 50V 10% X7R 0402; CAD_APPROVED: Yes; FPLIST: CC0402_25,CC0402_HD,0402_CC,capc0402_l; HEIGHT: 0.55 MM; MFG_NAME01: SAMSUNG; MFG_PN01: CL05B103KB5NNNC; Package Size: 0402; Polyhex_Number: PD.005.0006; ROHS: Yes; Tolerance: 10%; VOLTAGE: 50V
C234 C520 = CAP_NP: CAP CER 0.1uF 10V 20% X5R 0201; CAD_APPROVED: Yes; HEIGHT: 0.35MM; MFG_NAME01: SAMSUNG; MFG_PN01: CL03A104KP3NNNC; Package Size: 0201; Package Type: 7” reel; Polyhex_Number: PD.005.0054; ROHS: Yes; Tolerance: 20%; VOLTAGE: 10V
D32 = ZDIODE: DIODE ZNR 0.3W 3.3V 200mA AEC-Q101 SOD-523; AGILE_PN: 480-79870; CAD_APPROVED: Yes; HEIGHT: 0.65MM; MFG_NAME01: NEXPERIA; Polyhex_Number: PD.020.0074; ROHS: Yes; Temp Range: -65°C to +150°C; Temp_Range: -65°C to +150°C
HEAT1 = HEAT_26R00_27R50: HEAT 26R00x27R50x10R00 BLACK ALUMINUM; HEIGHT: 10mm; MFG_NAME01: RUNRONG; MFG_PN01: C275G100K260; Polyhex_Number: PW.006.0009
L19 L20 = INDUCTOR: IND -- 1.5UH@100KHZ 9A 20% SMT; AGILE_PN: 180-75776; CAD_APPROVED: Yes; HEIGHT: 3MM; MFG_NAME01: SUNLORD; MFG_PN01: MWSA0603S-1R5MT; PART_TYPE: POWER; Polyhex_Number: PD.012.0066; ROHS: Yes; Tolerance: 20%
L21 = INDUCTORS_OF_FERRITE: IND PWR 4.7uH@1MHz 2.3A 20% 4R00x4R00x3R00; Created by: YTL; DC Resistor: 0.06ohm; Irms: 2.3A; Isat: 2.9A; MFG_NAME01: SUNLORD; Part Type: POWER_IND; Polyhex_Number: PD.012.0021; Priority: A; Resonace frequency: 86M; Tolerance: 20%
Q5 = PMOS_NCE30P28Q: PMOS NCE30P28Q Vds=-30V Vgs=+/-20V, Id=-28A, QFN_3x3-8L, ncepower; MFG_NAME01: NCEPOWER; Polyhex_Number: PD.014.0020
Q6 = 2SK3018_SOT323: NMOS SW 30V 100mA SOT-323; MFG_NAME01: CHANGJING ELECTRONICS; Polyhex_Number: PD.014.0008
R592 R606 = RES: RES MF 3R3 1/10W 1% 0603; AGILE_PN: 470-77775; CAD_APPROVED: Yes; FPLIST: RC0603_OV,RC0603,0603_CC; HEIGHT: 0.55MM; MFG_NAME01: YAGEO; MFG_PN01: RC0603FR-073R3L; Polyhex_Number: PD.004.0335; ROHS: Yes; Temp Range: -55°C to +155°C; Temp_Range: -55°C to +155°C; Tolerance: 1%; VOLTAGE: 75V
R593 = RES: RES MF 10K 1/10W 5% 0603; AGILE_PN: 470-80526; CAD_APPROVED: Yes; FPLIST: RC0603_OV,RC0603,0603_CC; HEIGHT: 0.55 MM; MFG_NAME01: YAGEO; MFG_PN01: RC0603JR-0710KL; Polyhex_Number: PD.004.0332; ROHS: Yes; Tolerance: 1%; VOLTAGE: 75V
R594 R607 = RES: RES MF 499K  1/16W 1% 0402; AGILE_PN: 470-81910; ASSY_OPT: DNP; CAD_APPROVED: Yes; FPLIST: RC0402_25,RC0402_HD,0402_CC; HEIGHT: 0.40 MM; MFG_NAME01: YAGEO; MFG_PN01: RC0402FR-07499KL; Polyhex_Number: PD.004.0233; ROHS: Yes; Temp Range: -55C to +155C; Temp_Range: -55C to +155C; Tolerance: 1%; VOLTAGE: 50V
R595 R608 = RES: RES MF 43.0K 1/16W 1% 0402; AGILE_PN: 470-77562; CAD_APPROVED: Yes; FPLIST: RC0402_25,RC0402_HD,0402_CC; HEIGHT: 0.4MM; MFG_NAME01: YAGEO; MFG_PN01: RC0402FR-0743KL; Polyhex_Number: PD.004.0143; ROHS: Yes; Tolerance: 1%; VOLTAGE: 50V
R163 R165 R169 R596 R609 = RES: RES MF 10K 1/16W 5% 0402; AGILE_PN: 470-75557; CAD_APPROVED: Yes; FPLIST: RC0402_25,RC0402_HD,0402_CC; HEIGHT: 0.4 MM; MFG_NAME01: YAGEO; MFG_PN01: RC0402JR-0710KL; Polyhex_Number: PD.004.0010; ROHS: Yes; Tolerance: 5%; VOLTAGE: 50V
R597 R610 = RES: RES MF 499 OHM 1/16W 1% 0402; AGILE_PN: 470-30807; ASSY_OPT: DNP; CAD_APPROVED: Yes; FPLIST: RC0402_25,RC0402_HD,0402_CC; HEIGHT: 0.40 MM; MFG_NAME01: YAGEO; MFG_PN01: RC0402FR-07499RL; Polyhex_Number: PD.004.0117; ROHS: Yes; Tolerance: 1%; VOLTAGE: 50V
R598 R603 = RES: RES MF 22K 1/16W 5% 0402; AGILE_PN: 470-75609; CAD_APPROVED: Yes; FPLIST: RC0402_25,RC0402_HD,0402_CC; HEIGHT: 0.41mm; MFG_NAME01: YAGEO; MFG_PN01: RC0402JR-0722KL; Polyhex_Number: PD.004.0103; ROHS: Yes; Tolerance: 5%; VOLTAGE: 50V
R601 = RES: RES MF 5K6 1/16W 1% 0402; AGILE_PN: 470-30919; CAD_APPROVED: Yes; FPLIST: RC0402_25,RC0402_HD,0402_CC; HEIGHT: 0.40 MM; MFG_NAME01: YAGEO; MFG_PN01: RC0402FR-075K6L; Polyhex_Number: PD.004.0062; ROHS: Yes; Temp Range: -55°C ~ 155°C; Temp_Range: -55°C ~ 155°C; Tolerance: 1%; VOLTAGE: 50V
R602 = RES: RES MF 4K7 1/16W 5% 0402; AGILE_PN: 470-75557; CAD_APPROVED: Yes; HEIGHT: 0.4 MM; MFG_NAME01: YAGEO; MFG_PN01: RC0402JR-074K7L; Polyhex_Number: PD.004.0006; ROHS: Yes; Tolerance: 5%; VOLTAGE: 50V
R604 = RES: RES MF 1K 1/16W 5% 0402; ASSY_OPT: DNP; CAD_APPROVED: Yes; HEIGHT: 0.4 MM; MFG_NAME01: YAGEO; MFG_PN01: RC0402JR-071KL; Polyhex_Number: PD.004.0007; ROHS: Yes; Tolerance: 5%
R613 = RES: RES MF 9K31  1/16W 1% 0402; AGILE_PN: 470-30919; CAD_APPROVED: Yes; FPLIST: RC0402_25,RC0402_HD,0402_CC; HEIGHT: 0.40 MM; MFG_NAME01: YAGEO; MFG_PN01: RC0402FR-079K31L; Polyhex_Number: PD.004.0333; ROHS: Yes; Temp Range: -55°C ~ 155°C; Temp_Range: -55°C ~ 155°C; Tolerance: 1%; VOLTAGE: 50V
R614 = RES: RES MF 33R 1/16W 5% 0402; AGILE_PN: 470-75597; CAD_APPROVED: Yes; FPLIST: RC0402_25,RC0402_HD,0402_CC; HEIGHT: 0.40 MM; MFG_NAME01: YAGEO; MFG_PN01: RC0402JR-0733RL; Polyhex_Number: PD.004.0016; ROHS: Yes; Temp Range: -55C to +155C; Temp_Range: -55C to +155C; Tolerance: 5%; VOLTAGE: 50V
R615 = RES: RES MF 75K 1/16W 1% 0402; AGILE_PN: 470-75597; CAD_APPROVED: Yes; FPLIST: RC0402_25,RC0402_HD,0402_CC; HEIGHT: 0.40 MM; MFG_NAME01: YAGEO; MFG_PN01: RC0402FR-0775KL; Polyhex_Number: PD.004.0056; ROHS: Yes; Temp Range: -55C to +155C; Temp_Range: -55C to +155C; Tolerance: 1%; VOLTAGE: 50V
R617 = RES: RES MF 59K 1/16W 1% 0402; AGILE_PN: 470-75597; CAD_APPROVED: Yes; FPLIST: RC0402_25,RC0402_HD,0402_CC; HEIGHT: 0.40 MM; MFG_NAME01: YAGEO; MFG_PN01: RC0402FR-0759KL; Polyhex_Number: PD.004.0334; ROHS: Yes; Temp Range: -55C to +155C; Temp_Range: -55C to +155C; Tolerance: 1%; VOLTAGE: 50V
TP177-TP179 = TESTLOOP: TEST POINT PAD SIZE 4.7MM X 3.5MM SN TEST LOOP; AGILE_PN: 211-30043; CAD_APPROVED: Yes; HEIGHT: 2.286MM; MFG_NAME01: RONGHEWJ; PRIORITY_PN: 028-00650; Polyhex_Number: PD.010.0166; ROHS: Yes; Temp Range: -50°C to +146°C
TP182 TP184 = T_POINT_R: TEST POINT PAD .035 SMT, no part to order; AGILE_PN: 510-75618; ASSY_OPT: DNP; CAD_APPROVED: Yes; HEIGHT: 0.1MM; MFG_NAME01: NOT A COMPONENT; MFG_PN01: NOT A COMPONENT; Polyhex_Number: TEST POINT; ROHS: Yes
TVS7 = DIODE_TVS_BIDIR: DIODE SUPPRESSOR 16A@30NS 5V@1UA SOD-523; AGILE_PN: 480-76937; CAD_APPROVED: Yes; HEIGHT: 0.7MM; MFG_NAME01: on semiconductor; Polyhex_Number: PD.020.0077; ROHS: Yes
U105 = MP8759GD_QFN12P: IC VREG SYNC STEP DOWN DCDC ADJ 8A 4.5-26V QFN12; AGILE_PN: 315-81301; CAD_APPROVED: Yes; HEIGHT: 1.05 MM; MFG_NAME01: MONOLITHIC POWER SYSTEMS; Polyhex_Number: PD.008.0342; ROHS: Yes; Temp Range: -40°C to 125°C; Temp_Range: -40°C to 125°C; VOLTAGE: 4.5-26V
U106 = MP8759GD_QFN12P: IC VREG SYNC STEP DOWN DCDC ADJ 8A 4.5-26V QFN12; AGILE_PN: 315-81301; CAD_APPROVED: Yes; HEIGHT: 1.05 MM; MFG_NAME01: MONOLITHIC POWER SYSTEMS; Polyhex_Number: PD.008.xxxx; ROHS: Yes; Temp Range: -40°C to 125°C; Temp_Range: -40°C to 125°C; VOLTAGE: 4.5-26V
U107 = REF8320: 2A 26V SYNCHRONOUS STEP-DOWN CONVERTER; MFG_NAME01: REFSEMI; Polyhex_Number: PD.008.0318
C227 = CAP_NP: CAP CER 4.7UF 50V 10% X5R 0805; CAD_APPROVED: Yes; MFG_NAME01: SAMSUNG; MFG_PN01: CL21A475KBQNNNE; Polyhex_Number: PD.005.0064; ROHS: Yes; Tolerance: 10%; VOLTAGE: 50V
C231 C236 = CAP_NP: CAP CER 2.2uF 10V 10% X5R 0402; CAD_APPROVED: Yes; FPLIST: CC0402_25,CC0402_HD,0402_CC,capc0402_l; HEIGHT: 0.55 MM; MFG_NAME01: SAMSUNG; MFG_PN01: CL05A225KO5NQNC; Package Size: 0402; Polyhex_Number: PD.005.0041; ROHS: Yes; Tolerance: 10%; VOLTAGE: 16V
C235 = CAP_NP: CAP CER 1uF 50V 10% X5R 0603; CAD_APPROVED: Yes; FPLIST: CC0603_OV,CC0603,0603_CC; HEIGHT: 0.9MM; MFG_NAME01: SAMSUNG; MFG_PN01: CL10A105KB8NNNC; Package Size: 0603 (1608 Metric); Package Type: Surface Mount, MLCC; Polyhex_Number: PD.005.0063; ROHS: Yes; Rated Voltage: 50V; Temp Range: -55C to +125C; Tolerance: 10%; VOLTAGE: 50V
D3 = DIODE: SMAG PLASTIC ENCAPSULATE DIODES IF=5A VRMS=42V; MFG_NAME01: JSCJ-ELEC; Polyhex_Number: PD.020.0046
D4 D5 D31 = DIODE: DIODE SCH 30V 200MA -- SOD323; AGILE_PN: 480-30039; CAD_APPROVED: Yes; HEIGHT: 1.15MM; MFG_NAME01: ON SEMICONDUCTOR; Polyhex_Number: PD.020.0073
F1 F2 = FUSE: FUSE HIGH I2T 7A 32V 1206; AGILE_PN: 510-77913; CAD_APPROVED: Yes; HEIGHT: 0.8639MM; MFG_NAME01: LITTELFUSE; MFG_PN01: 0440007.WR; Polyhex_Number: PD.004.0322; ROHS: Yes
J1 = CONN_HDR_2X1: CON 1X2 PLUG SHRD TH 2.5MM SP 290H SN 134L; AGILE_PN: 210-82579; CAD_APPROVED: Yes; HEIGHT: 7.36MM; MFG_NAME01: WENZHANGJIMEI; MFG_PN01: 5001-HA0025C-2P1-00; Package Type: Through Hole; Polyhex_Number: PD.011.0166; ROHS: Yes; Temp Range: -25C to +85C
J2 = HYTP-SMT1-2151: CON 16PIN USB TYPE C SMT; HEIGHT: 3.16mm; MFG_NAME01: HUAYAO; Polyhex_Number: PD.010.0129; ROHS: YES; Temp Range: -25C to +85C; Temp_Range: -25C to +85C
Q7 Q8 = NX3008NBKW_SOT323: TRAN NMOS SW 30V 350mA AEC-Q101 SC-70; AGILE_PN: 480-79736; CAD_APPROVED: Yes; HEIGHT: 1.1MM; MFG_NAME01: NEXPERIA; Polyhex_Number: PD.014.0033; ROHS: Yes
R157 R158 = RES: RES MF ZERO OHM JUMPER 1/4W 5% 1206; CAD_APPROVED: Yes; HEIGHT: 0.6MM; MFG_NAME01: YAGEO; MFG_PN01: RC1206FR-070RL; Polyhex_Number: PD.004.0214; ROHS: Yes; Temp Range: -55 °C to +155 °C; Temp_Range: -55 °C to +155 °C; Tolerance: 5%; VOLTAGE: 200V
R168 = RES: RES MF 10K 1/16W 5% 0402; AGILE_PN: 470-75557; ASSY_OPT: DNP; CAD_APPROVED: Yes; FPLIST: RC0402_25,RC0402_HD,0402_CC; HEIGHT: 0.4 MM; MFG_NAME01: YAGEO; MFG_PN01: RC0402JR-0710KL; Polyhex_Number: PD.004.0010; ROHS: Yes; Tolerance: 5%; VOLTAGE: 50V
R585 R586 = RES: RES MF ZERO OHM 1/20W 5% 0201; AGILE_PN: 470-82323; ASSY_OPT: DNP; CAD_APPROVED: Yes; FPLIST: RC0201,0201_CC; HEIGHT: 0.26MM; MFG_NAME01: YAGEO; MFG_PN01: RC0201JR-070RL; Polyhex_Number: PD.004.0171; ROHS: Yes; Temp Range: -55°C ~ 125°C; Temp_Range: -55°C ~ 125°C; Tolerance: 5%; VOLTAGE: 25V
R629 = RES: RES MF 47K 1/10W 5% 0603; AGILE_PN: 470-75557; ASSY_OPT: DNP; CAD_APPROVED: Yes; HEIGHT: 0.4 MM; MFG_NAME01: YAGEO; MFG_PN01: RC0603JR-0747KL; Polyhex_Number: PD.004.0329; ROHS: Yes; Tolerance: 5%; VOLTAGE: 75V
SW3 = SW_DPDT_3: SW DPDT SLD 0.1A 12V TH; AGILE_PN: 510-78053; CAD_APPROVED: Yes; HEIGHT: 5.8MM; MFG_NAME01: HUIZHOU LIAN RUI XING; Polyhex_Number: PD.011.0177; ROHS: Yes
U9 = NX20P5090UK_15P_A: IC USB PWR SW 5A 2.5-20V WLCSP15; AGILE_PN: 315-81116; MFG_NAME01: NXP SEMICONDUCTORS; Polyhex_Number: PD.008.0306
U10 = PTN5110_QFN16: IC USB PD PHY 1PORT 2.7-5.5V HX2QFN16; AGILE_PN: 315-81118; CAD_APPROVED: Yes; HEIGHT: 0.4MM; MFG_NAME01: NXP SEMICONDUCTORS; Polyhex_Number: PD.008.0307; ROHS: Yes; Temp Range: ¨C40C to +85C; Temp_Range: ¨C40C to +85C; VOLTAGE: 2.7-5.5V
U11 = NX20P0407_WLCSP12_A: IC USB TYPE C PROTECTION +15KV/+8KV ESD WLCSP12; AGILE_PN: TMP-WF-31350; CAD_APPROVED: Yes; HEIGHT: 0.565 MM; MFG_NAME01: NXP SEMICONDUCTORS; PRE_APN: 312-81846; Polyhex_Number: PD.008.0308; ROHS: Yes; Temp Range: -40C to +85C; VOLTAGE: +15KV/+8KV
U12 = LDO_SOT23_5: IC LIN VREG 3.3V 150mA 30V SOT23-5; MFG_NAME01: TI; Polyhex_Number: PD.008.0194

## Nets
3V3_PG: TP184.1(TP) U106.3(PG)
5V_PG: TP182.1(TP) U105.3(PG)
GND: BH3.1(NC) BH4.1(NC) BH5.1(NC) BH6.1(NC) BH11.1 BH12.1 C125.2 C126.2 C127.2 C129.2 C130.2 C131.2 C132.2 C133.2 C135.2 C136.2 C137.2 C138.2 C139.2 C140.2 C141.2 C142.2 C143.2 C144.2 C145.2 C146.2 C147.2 C148.2 C149.2 C150.2 C151.2 C152.2 C153.2 C154.2 C155.2 C156.2 C157.2 C166.2 C167.2 C170.2 C171.2 C172.2 C179.2 C180.2 C197.2 C198.2 C199.2 C227.2 C228.2 C229.2 C230.2 C231.2 C232.2 C233.2 C234.2 C235.2 C236.2 C496.2 C498.2 C499.2 C500.2 C501.2 C504.2 C505.2 C506.2 C507.2 C508.2 C510.2 C512.2 C513.2 C514.2 C515.2 C516.2 C517.2 C519.2 C520.2 C521.2 D32.A(ANODE) HEAT1.1 HEAT1.2 J1.2 J2.1(SH1) J2.2(SH2) J2.3(SH3) J2.4(SH4) J2.A1B12(AGND) J2.B1A12(BGND) Q6.2(SOURCE) Q7.2(SOURCE) Q8.2(SOURCE) R80.2 R81.2 R82.2 R83.2 R162.2 R164.2 R168.2 R600.2 R601.2 R605.2 R612.2 R613.2 R617.2 R618.2 R629.2 TP36.1(Pin1) TP37.1(Pin1) TP38.1(Pin1) TP39.1(Pin1) TP48.1(Pin1) TP177.1(Pin1) TP178.1(Pin1) TP179.1(Pin1) TVS7.1(A1) U6.5(AGND) U6.30(R_SNSP3_CFG) U6.43(BUCK_AGND) U6.57(EPAD) U9.C3(GND1) U9.D3(GND2) U9.E3(GND3) U10.17(GND) U11.B3(GND) U11.D3(SBUEN) U12.2(GND) U105.2(PGND) U105.10(AGND) U106.2(PGND) U106.10(AGND) U107.2(GND) ; also on sheet 4 5 7 8 13 14 15 16 17 18 19 20 21 22 23 24 25 26 27
VBUS_IN: C170.1 C171.1 C172.1 C197.1 C198.1 C199.1 C228.1 C229.1 C496.1 C510.1 D3.2(K) R157.2 R158.2 R593.1 TP185.1(Pin1) U105.1(VIN) U106.1(VIN) ; also on sheet 13 20
VBUS_OVLO_TH: R159.2 R162.1 U9.B3(OVLO)
VCC_3V6_1: C505.1 R599.1 U105.9(VCC)
VCC_3V6_2: C517.1 R611.1 U106.9(VCC)
VCC_EXT_1V8: C519.1 C520.1 L21.2 R615.1 ; also on sheet 20 21
VCC_EXT_3V3: C511.2 C512.1 C513.1 C514.1 C515.1 L20.2 R608.1 TP183.1(Pin1) U106.5(VOUT) ; also on sheet 19 20 21 23 24 25 27
VDD_1V8: C146.1 C147.1 L8.2 R61.1 R76.1 R77.1 R78.1 R79.1 R628.1 TP33.1(Pin1) U6.14(BUCK5FB) ; also on sheet 4 5 6 16 18 21 22 23 24 25 26 27
VDD_3V3: C141.1 C142.1 C152.1 C232.1 L7.2 R85.1 R87.1 R165.1 R169.1 R603.1 R609.1 R616.1 TP31.1(Pin1) U6.21(BUCK4FB) U6.22(SWIN) U10.3(VDD) ; also on sheet 4 13 14 15 16 17 18 20 22 24 26 27
VDD_5V: C233.1 C503.1 C506.1 C507.1 Q5.5(DRAIN5) Q5.6(DRAIN6) Q5.7(DRAIN7) Q5.8(DRAIN8) TP181.1(Pin1) U10.12(VCONN_IN) ; also on sheet 13 18 19 20 24 27
VDD_ARM: C126.1 C127.1 L4.2 R50.1 R51.2 TP25.1(Pin1) ; also on sheet 4
VDD_SOC: C130.1 C131.1 C136.1 C137.1 L5.2 L6.2 R52.1 R53.2 TP27.1(Pin1) ; also on sheet 4
VDDA_1V8: C139.1 TP30.1(Pin1) U6.54(LDO3) ; also on sheet 4
VINT: C155.1 U6.4(VINT)
BOOT_MODE0: R83.1 SW5.4(A4) ; also on sheet 8
BOOT_MODE1: R82.1 SW5.3(A3) ; also on sheet 8
BOOT_MODE2: R81.1 SW5.2(A2) ; also on sheet 8
BOOT_MODE3: R80.1 SW5.1(A1) ; also on sheet 8
DCDC_5V: C179.1 C180.1 C497.2 C498.1 C499.1 C500.1 C501.1 C502.1 FB1.1 L19.2 Q5.1(SOURCE1) Q5.2(SOURCE2) Q5.3(SOURCE3) R595.1 R598.1 TP180.1(Pin1) U105.5(VOUT) U107.5(VIN) ; also on sheet 13 14 17
I2C1_SCL: R62.1 R84.1 ; also on sheet 6 26
I2C1_SCL_3V3: R89.2 R170.1 ; also on sheet 13
I2C1_SDA: R64.1 R86.1 ; also on sheet 6 26
I2C1_SDA_3V3: R88.2 R171.1 ; also on sheet 13
NVCC_DRAM_1V1: C150.1 C151.1 L9.2 TP35.1(Pin1) U6.52(BUCK6FB) ; also on sheet 4 5
NVCC_SD2: C148.1 TP34.1(Pin1) U6.55(LDO5) ; also on sheet 4 6 13
NVCC_SNVS_1V8: C132.1 R55.1 TP28.1(Pin1) U6.3(LDO1) ; also on sheet 4 8
PD_BYPASS: C231.1 U10.4(BYPASS)
PD_DBG_ACC: TP66.1(Pin1) U10.9(DBG_ACC)
PD_EN_SINK: R163.1 U10.2(EN_SNK1) ; also on sheet 13
PD_EN_SRC: TP64.1(Pin1) U10.16(EN_SRC)
PD_FRS_EN: TP65.1(Pin1) U10.1(FRS_EN)
PD_I2C_SCL: R170.2 U10.8(I2C_SCL)
PD_I2C_SDA: R171.2 U10.7(I2C_SDA)
PD_ILIM_5V_VBUS: TP67.1(Pin1) U10.6(ILIM_5V_VBUS)
PD_LD_nFLT: R167.2 U10.11(FAULT_N)
PD_USB_CC1: R585.2 U10.13(CC1) U11.A2(CC1)
PD_USB_CC2: R586.2 U10.14(CC2) U11.B2(CC2) U11.C1(CON_SBU1) U11.C2(SBU1)
PD_USB_VBUS_IN: R157.1 R158.1 TP60.1(Pin1) U9.A1(VINT1) U9.B1(VINT2) U9.C1(VINT3) U9.D1(VINT4)
PD_VBUS_PG: Q8.1(GATE) R166.2 R628.2 TP63.1(Pin1) U9.A2(ACK)
PMIC_32K_OUT: R75.2 ; also on sheet 26
PMIC_nINT: U6.13(IRQ_B) ; also on sheet 6
PMIC_ON_REQ: R57.1 R604.1 ; also on sheet 8
PMIC_STBY_REQ: R58.1 ; also on sheet 8
POE_PD: D31.A F1.1 J1.1
POR_B: R63.2 ; also on sheet 8 24 26
SD2_RESET_B: R54.1 ; also on sheet 6
SD2_VSEL: U6.29(SD_VSEL) ; also on sheet 6
SYS_nRST: R56.1 TP40.1(Pin1) ; also on sheet 24 27
TCPC_nINT: R169.2 TP68.1(Pin1) U10.10(ALERT_N) ; also on sheet 6
USB_CC1_CN: J2.A5(ACC1) SW3.3(NO1)
USB_CC1_ESD: R585.1 SW3.2(COMMON1) U11.A1(CON_CC1)
USB_CC2_CN: J2.B5(BCC1) SW3.6(NO2)
USB_CC2_ESD: R586.1 SW3.5(COMMON2) U11.B1(CON_CC2)
USB_PD_VBUS: F2.1 J2.A4B9(AVBUS) J2.B4A9(BVBUS) TP59.1(Pin1)
USB_PD_VBUS_F: C227.1 D4.A F2.2 R159.1 R160.1 R629.1 U9.B2(VBUS1) U9.C2(VBUS2) U9.D2(VBUS3) U9.E1(VBUS4) U9.E2(VBUS5) U10.15(VBUS)
USB_SBU1: J2.A8(ASBU1) TP61.1(Pin1)
USB_SBU2: J2.B8(BSBU1) TP62.1(Pin1)
USBC_VBUS_F: D5.A ; also on sheet 13
VLDO_3V3: C234.1 C236.1 R161.1 R166.1 U11.A3(VSYS) U12.5(OUT) ; also on sheet 13 24
VSD_3V3: C153.1 U6.23(SWOUT) ; also on sheet 27
VSYS_5V: C125.1 C129.1 C133.1 C135.1 C140.1 C143.1 C145.1 C149.1 C154.1 C166.1 C167.1 FB1.2 TP47.1(Pin1) U6.16(INB45_1) U6.17(INB45_2) U6.18(INB45_3) U6.33(INB13_1) U6.34(INB13_2) U6.35(INB13_3) U6.47(INB26_1) U6.48(INB26_2) U6.49(INB26_3) U6.53(VSYS) U6.56(INL1)
WDOG_B: R60.1 TP41.1(Pin1) ; also on sheet 6
XIN_32K: C156.1 QZ1.2 R65.1 U6.10(XTAL_IN)
XOUT_32K: C157.1 QZ1.1 R65.2 U6.11(XTAL_OUT)
N106651228: L4.1 U6.45(LX2_1) U6.46(LX2_2)
N106658448: L5.1 U6.36(LX1_1) U6.37(LX1_2)
N106658526: R52.2 R53.1 U6.38(R_SNSP1)
N106658680: R50.2 R51.1 U6.44(R_SNSP2)
N106678828: L9.1 U6.50(LX6_1) U6.51(LX6_2)
N106678929: L7.1 U6.19(LX4_1) U6.20(LX4_2)
N106679105: L6.1 U6.31(LX3_1) U6.32(LX3_2)
N106679133: L8.1 U6.15(LX5)
N107591800: C138.1 TP29.1(Pin1) U6.2(LDO2)
N108986859: R62.2 U6.41(SCL)
N108986878: R64.2 U6.42(SDA)
N108987071: R57.2 U6.39(PMIC_ON_REQ)
N108987090: R58.2 U6.40(PMIC_STBY_REQ)
N108987195: R60.2 R61.2 U6.28(WDOG_B)
N108987391: R55.2 R56.2 U6.8(PMIC_RST_B)
N108988596: R63.1 U6.9(POR_B)
N109012947: C144.1 TP32.1(Pin1) U6.1(LDO4)
N109024867: R54.2 U6.12(SW_EN)
N109453317: R84.2 U6.27(SCLL)
N109453320: R86.2 U6.26(SDAL)
N109453344: R87.2 R88.1 U6.24(SDAH)
N109453357: R85.2 R89.1 U6.25(SCLH)
N109837143: R75.1 U6.7(CLK_32K_OUT)
N110641885: Q7.3(DRAIN) R160.2 R161.2 U9.A3(\\~{E}N)
N110642020: TP69.1(Pin1) U11.C3(FLAG)
N110642027: C230.1 Q7.1(GATE) R163.2 R164.1
N110642138: Q8.3(DRAIN) R165.2 R167.1
N110642381: R168.1 U10.5(SLV_ADDR)
N110645352: C235.1 D4.C(K) D5.C(K) D31.C(K) R172.1 U12.1(IN)
N110684056: R172.2 U12.3(EN)
N111194517: R76.2 SW5.8(B1)
N111194520: R77.2 SW5.7(B2)
N111194523: R78.2 SW5.6(B3)
N111194526: R79.2 SW5.5(B4)
N111425461: D3.1 F1.2
N112515832: R599.2 R600.1 U105.6(MODE)
N112515848: R595.2 R597.2 R601.1 U105.11(FB)
N112515850: C495.2 L19.1 R594.1 U105.7(SW)
N112515852: C495.1 R592.2
N112515856: R592.1 U105.8(BST)
N112515862: C504.1 D32.C(CATHODE) R593.2 R596.1 TVS7.2(A2)
N112516038: C497.1 R594.2 R597.1
N112516056: R596.2 U105.12(EN)
N112519774: R611.2 R612.1 U106.6(MODE)
N112519796: R608.2 R610.2 R613.1 U106.11(FB)
N112519798: C509.2 L20.1 R607.1 U106.7(SW)
N112519800: C509.1 R606.2
N112519804: R606.1 U106.8(BST)
N112519986: C511.1 R607.2 R610.1
N112520004: C516.1 R609.2 U106.12(EN)
N112527218: C521.1 R616.2 R618.1 U107.4(EN)
N112527252: L21.1 R614.2 U107.6(SW)
N112527265: C518.1 U107.1(BST)
N112527267: C518.2 R614.1
N112527275: R615.2 R617.1 U107.3(FB)
N112531573: C508.1 Q6.1(GATE) R603.2 R604.2 R605.1
N112531579: C502.2 C503.2 Q5.4(GATE) R598.2 R602.1
N112531583: Q6.3(DRAIN) R602.2

Not connected (* = marked no-connect by the designer): J2 A6(ADP1)* A7(ADN1)* B6(BDP1)* B7(BDN1)* M1* M2*; SW3 1(NC1)* 4(NC2)*; U6 6(RTC_RESET_B)*; U11 D1(CON_SBU2)* D2(SBU2)*; U12 4(NC)*; U105 4(NC)*; U106 4(NC)*

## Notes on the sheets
sheet 9
- Boot Mode and CFG Switch
- i.MX8M Plus ROM Fuse
- i.MX8M Plus Boot Mode
- Full Line
  Address
- Physical
  Address
- 7
- 6
- 5
- 4
- 3
- 2
- 1
- 0
- BOOT_MODE3
- BOOT_MODE2
- BOOT_MODE1
- BOOT_MODE0
- Boot Modes
- OVERRIDE_FLEXSPI_BT_SEL_VAL
  00 - FlexSPI (Hyperflash 1.8V)
  01 - FlexSPI (Flash with 4B READ(1x13 default
  supported)
  10 - Default Octal mode (Micron, supported on
  8QXP B0 already)
  11 - Default Octal mode (Mxic, Nice to have)
- OVERRIDE_NAND_PG_PER_BLK_VAL
  00 - 32 pages
  01 - 64 pages
  10 - 128 pages
  11 - 32 pages
- OVERRIDE_FLEXSPI_BT_SEL
  0 - Do not overriude
  1 - Override
- FLEXSPI_AUTO_PROBE_EN
  0 - Disable
  1 - Enable
- FLEXSPI_AUTO_PROBE_TYPE
  00 - QuadSPI NOR
  01 - MxicOctal
  10 - MicronOctal
  11 - AdestoOctal
- 0x470[15:0]
- 0x470[7:0]
- 0
- 0
- 0
- 0
- Boot From Internal Fuses
- FLEXSPI_FEQ_SEL
  000 - 100 MHz
  001 - 133 MHz
  010 - 166 MHz
  011 - 200 MHz
  100 -  80 MHz
  101 -  20 MHz
- 0
- 0
- 0
- 1
- USB Serial Download
- 0x480[15:0]
- 0x480[7:0]
- Reserved
- FLEXSPI_DUMMY_CYCLE_SEL
- 0
- 0
- 1
- 0
- USDHC3 (eMMC boot only, SD3 8-bit)
  Default
- ROM_NO_LOG
  if blown, ROM will not
   log event to log buffer
- SDP_DISABLE
  Disable USB serial
   download
- FORCE_BT_FROM_FUSE
  Boot from programmed
   fuses, not Boot Mode Pins
- FLEXSPI_HOLD_TIME_SEL
  00 - 500us
  01 - 1ms
  10 - 3ms
  11 - 10ms
- WDOG_TIMEOUT_SELECT
  00 - 2.0s
  01 - 1.5s
  10 - 1.0s
  11 - 0.5s
- 0
- 0
- 1
- 1
- USDHC2 (SD boot only, SD2)
- 0x480[31:16]
- 0x480[23:16]
- NOC_ID_REMAP_BYPASS
- 0
- 1
- 0
- 0
- NAND 8-bit single device 256 page
- SDMMC_BUS_WIDTH
  00 - 8-bit
  01 - 4-bit
  10 - 8-bit DDR (MMC 4.4)
  11 - 4-bit DDR (MMC 4.4)
- SD_SPEED:
  00 - Normal/SDR12
  01 - High/SDR25
  10 - SDR50
  11 - SDR104
- USDHC_VOL_SEL
  For Normal Boot Mode
   IO Voltage
  0 - 3.3V
  1 - 1.8V
- USDHC_MFG_VOL_SEL
  For Mfg Mode IO Voltage
  0 - 3.3V
  1 - 1.8V
- USDHC_PWR_EN
  0 - No power cycle
  1 - Enabled via
- EMMC_FAST_BT
  0 - Regular
  1 - Fast Boot
- EMMC_SPEED:
  00 - Normal
  01 - High
- 0x490[15:0]
- 0x490[7:0]
- 0
- 1
- 0
- 1
- NAND 8-bit single device 512 page
- RECOVERY_SDMMC
  _BOOT_DIS
  0 - Enable
   1 - Disable
- USDHC_DLL_EN
  0 - Disable DLL for
  SD/eMMC
  1 - Enable DLL for
  SD/eMMC
- 0
- 1
- 1
- 0
- QSPI 3B Read
- USDHC_PAD_SION_EN
  0 - Disable
  1 - Enable
- 0x490[31:16]
- 0x490[23:16]
- BT_RDC_DISABLE
- IMG_CNTN_SET1_OFFSET
- 0
- 1
- 1
- 1
- QSPI Hyperflash 3.3V
- USDHC_PWR_INTERVAL
  00 - 20ms
  01 - 10ms
  10 - 5ms
  11 - 2.5ms
- SD_CALI_STEP
  '00' - 1
  TBD
- USDHC_PWR_DELAY
  0 -  5ms
  1 - 2.5ms
- USDHC_PWR_POLARITY
  0 - Low
  1 - High
- EMMC_FAST_BT_ACK
  0 - Boot Ack Disabled
  1 - Boot Ack Enabled
- 0x4A0[15:0]
- 0x4A0[7:0]
- USDHC_OVRD_
  PAD_SETTING_UP1
- 1
- 0
- 0
- 0
- ecSPI Boot
- 1
- 0
- 0
- 1
- Reserved
- 0x4A0[31:16]
- 0x4A0[23:16]
- Reserved
- NAND_GPMI_DDR_DLL_VAL
  (GPMI Read DDR DLL Target Value)
  0000 - 7
  0001 - 1
  0111 - 0
  1111 - 15
- NAND_CS_NUM
  (Nand Number Of Devices)
  00 - 1
  01 - 2
  10 - 4
  11 - Reserved
- 1
- 0
- 1
- 0
- FLEXSPI Serial NAND  2k page
- 0x4B0[15:0]
- 0x4B0[7:0]
- Reserved
- USB_SS_ENABLE
- 1
- 0
- 1
- 1
- FLEXSPI Serial NAND  4k page
- FlexSPI NAND CS Interval
  00-100ns
  01-200ns
  10-400ns
  11-50ns
- FlexSPI NAND Column Address Width
  00-12
  01-13
  10-14
  11-15
- 0x4B0[31:16]
- 0x4B0[23:16]
- Reserved
- FlexSPI NAND Busy Bit Offset Override
- 1
- 1
- 0
- 0
- Reserved
- 1
- 1
- 0
- 1
- Reserved
- 7
- 6
- 5
- 4
- 3
- 2
- 1
- 0
- Full Line
  Address
- Physical
  Address
- 1
- 1
- 1
- 0
- Reserved
- BOOT_MODE_FUSES
  BootRom will retrieve boot mode from these fuses instead of BOOT_MODE pins if
  * BOOT_MODE_PINS=0x0 or * BT_FUSE_SEL blown
- OVERRIDE_USDHC_BT_SEL
  0 - Do not override
  1 - Override
- OVERRIDE_USDHC_BT_SEL_VAL
  00 - uSDHC1 SD
  01 - uSDHC1 eMMC
  10 - uSDHC2 eMMC
  11 - uSDHC3 SD
- 0x470[15:0]
- 0x470[15:8]
- OVERRIDE_NAND_PG_PER_BLK
  0 - Do not override
  1 - Override
- 1
- 1
- 1
- 1
- Reserved
- BT_LPB (Core/DDR/Bus)
  '00'/'01' - LPB Disable
  '10' - Div by 2
  '11' - Div by 4
- BT_FREQ_SEL
  (ARM/DDR)
  0 - 800 / 800 MHz
  1 - 400 / 400 MHz
- BT_LPB_POLARITY
  (GPIO polarity)
- ICACHE_DIS
  L1 I-Cache
  DISABLE
- WDOG_EN
  '0' - Disabled
  '1' - Enabled
- DCACHE_DIS
  Disable L1 and L2 D-Cache
- 0x480[15:0]
- 0x480[15:8]
- TZASC_EN
- ECSPI_PORT_SEL
  000 - eCSPI1
  001 - eCSPI2
  010 - eCSPI3
- ECSPI_CS_SEL(SPI only)
  00 - CS#0 (default)
  01 - CS#1
  10 - CS#2
  11 - CS#3
- ECSPI_ADDR_SEL
  0 - 3-bytes (24-bit)
  1 - 2-bytes (16-bit)
- RECOVER_ECSPI_BOOT_EN
  '0' - Disabled
  '1' - Enabled
- 0x480[31:16]
- 0x480[31:24]
- DCACHE_BYPASS_DIS
- USDHC_DLL_SEL
  0 - DLL Slave Mode for
  1 - DLL Override Mode
- SDMMC_DLL_DLY[6:0]
  Delay target for USDHC DLL, it is applied to slave mode target delay
  or override mode target delay depends on DLL Override fuse bit value.
- 0x490[15:0]
- 0x490[15:8]
- 0x490[31:16]
- 0x490[31:24]
- USDHC_OVRD_PAD_SETTING_LOW8[7:0]
- NAND_TG_PREAMBLE_RD_LATENCY
  (Toggle Mode 33MHz Preamble Delay, Read Latency)
   '000' - 16 GPMICLK cycles.
  '001' - 1 GPMICLK cycles.
   '010' - 2 GPMICLK cycles.
   '011' -  3 GPMICLK cycles.
   '100' - 4 GPMICLK cycles.
  '101' - 5 GPMICLK cycles.
   '110' - 6 GPMICLK cycles.
  '111' - 7 GPMICLK cycles.
  '1111'- 15  GPMICLK cycles.
- NAND_FCB_SERCH_COUNT
  00 - 2
  01 - 2
  10 - 4
  11 - 8
- 0x4A0[15:0]
- 0x4A0[15:8]
- BT_TOGGLE_MODE
- NAND_RST_TIME
- 0x4A0[31:16]
- 0x4A0[31:24]
- NAND_OVERRIDE_PAD_SETTING[7:0]
- NAND_READ_RETRY_SEQ_ID[3:0]
  0000 - don't use read retry(RR) sequence embedded in ROM
  0001 - Micron 20nm RR sequence
  0010 - Toshiba A19nm RR sequence
  0011 - Toshiba 19nm RR sequence
  0100 - SanDisk 19nm RR sequence
  0101 - SanDisk 1ynmRR sequence
  0110 - Hynix 20nm A Die RR sequence
  0111 - Hynix 26nm RR sequence
  1000 - Hynix 20nm B Die RR sequence
  1001 - Hynix 20nm C Die RR sequence
  Others - Reserved
- NAND_ROW_ADDR_BYTES
  00 - 3
  01 - 2
  10 - 4
  11 - 5
- 0x4B0[15:0]
- 0x4B0[15:8]
- Reserved
- Reserved
- 0x4B0[31:16]
- 0x4B0[31:24]
- RNG_TRIM[7:0]
sheet 10
- SYS PMIC
- 0.8/0.9/1.0V 3A
- 1.8V 10mA
- 0.8V 10mA
- No need for 8M Plus
- Sense from Processor power pin
- 0.8/0.9V 3A
- 1.8V 300mA
- Buck1&3
  Dual Phase Mode
- Sense from Processor power pin
- 0.8/0.9V 3A
- 0.8V 200mA
- No need for 8M Plus
- 3.3V/1.8V 150mA
- Sense connect to GND for dual phase mode
- 3.3V 3A
- GND Testpoints
- Backup PWR Supply
- 1.8V 2A
- 1.1V 2A
- 3.3V 400mA
- i.MX8M Plus LPDDR4 EVK Power Sequence and Operating Range
- SEQ
- PWR/Signal
- REG
- MIN
- TYP
- MAX
- Max Current(mA)
- 1
  2
  3
  4
  5
  6
  7
  8
  8
  9
  10
- NVCC_SNVS_1V8
  32K_INTERNAL
  VDD_SOC
  VDD_ARM
  VDDA_1V8
  VDD_1V8/NVCC_xxx
  NVCC_DRAM_1V1
  VDD_3V3/NVCC_xxx
  VSD_3V3
  NVCC_SD2
  POR_B
- LDO1
  RTC_CLK
  BUCK1/3
  BUCK2
  LDO3
  BUCK5
  BUCK6
  BUCK4
  MUXSW
  LDO5
  POR_B
- 1.71
  --
  0.805/0.9
  0.805/0.9/0.95
  1.71
  1.65
  1.045
  3
  3
  3.0/1.65
  --
- 1.8
  --
  0.85/0.95
  0.85/0.95/1.0
  1.8
  1.8
  1.1
  3.3
  3.3
  3.3/1.8
  --
- 1.95
  --
  0.9/1.0
  0.9/1.0/1.05
  1.89
  1.95
  1.155
  3.6
  3.6
  3.6/1.95
  --
- 10
  --
  6000
  3000
  300
  2000
  2000
  3000
  400
  150
  --
- # System Reset Button
- PU
- Internal LDO
- # CPU WDOG_B Reset
- OD + PU
- OD
- Configure internal pull up at CPU side
- OD
- Note:
- 1. PMIC_RST_B is used as Cold Reset as default.
- 2. WDOG_B is used as Cold Reset, external pull up is needed for BSDL mode.
sheet 11
- 8A is maximum capability of the regulator
  System current TBD
- Main PWR (5-20V-->5V)
- # EN: 1.35V-4.5V
- # EN: internal 600K PD
- R1
- Vfb=600mV
- VOUT=0.6*(1+43K/5K6)=5.207V
- Vout = (R1+R2) * Vfb / R2
- # 5.2V/8A
- Vds=-30V, Id=-28A
  Rds<9 mOhm@ Vgs -10V
  Rds<19 mOhm@ Vgs -4.5V
  Vgs(th) = -1.7V min
- R2
- Main PWR (5-20V-->3.3V)
- 8A is maximum capability of the regulator
  System current TBD
- # EN: 1.35V-4.5V
- # EN: internal 600K PD
- R1
- Vfb=600mV
- VOUT=0.6*(1+43K/9K31)=3.371V
- # 3.37V/8A
- Vout = (R1+R2) * Vfb / R2
- R2
- FB=0.8V
- VOUT=(1+75K/59K)*0.8V=1.82V
- # Standoff for HEAT1 M2.5
- Base board screw holes
- GND Testpoints
sheet 12
- POE PD Power Supply
- 6.0A
- For discharge
- #Power Good Acknowledge (open-drain output)
- #'L' for PWR GOOD
- VOVLO threshold input
- CC OVP
- I/OD
- O
- O
- SLV_ADDR
- Dev ADDR
- GND
- 1010000x
- SYS PWR Switch
- #default "L"
- 10 K pull-up to BYPASS
- 1010001x
- O
- Unconnected
- 1010010x
- 100 K pull-up to BYPASS
- 1010011x
- O/OD
- I2C_3.3V
- Control CC for Type-C PD power on/off control
- default "UFP" mode
- 1-2/4-5   OFF Default
- 3-2/6-5    ON
- # I2C ADDR: 0b'10100[10]X
- Always ON LDO
- # This LDO is used for preventing the Ld SW
  NX20P3483UK enter into dead battery mode.
- #C1 C2 PIN used for layout convenient
